(* Logix 5000 project; controller Test vendor 1 type 14 code 92 rev 33.11; software revision 33.00 *)

TASK MainTask (continuous, watchdog 500 ms) : MainProgram

MODULES
   Local : vendor 1 type 14 code 92 (ICP 0, rev 33.11)
      IN : vendor 1 type 7 code 1 (ICP 3, rev 3.2, Input RPI 20 ms)
      O : vendor 1 type 7 code 15 (ICP 2, rev 3.2, Output RPI 20 ms)
      Ethernet : 1756-ENBT (ICP 1, Ethernet 192.168.0.98, rev 6.4)
         IOLM1 : DXM (Ethernet 192.168.0.1, rev 2.22, StandardDataDriven RPI 20 ms)
END_MODULES

TYPE Banner_IOL_Port_v4 :   // UDT that has all of the data items necessary to communicate with a specific Port on a IO-Link Master
STRUCT
   Port_Controlled : INT;   // Each bit represents a port on an IO-Link Master. Set to 1 to tell AOI to control that port.
   Port_Activate : INT;   // Each bit represents a port on an IO-Link Master. When ON that port will process any commands in queue.
   Port_Read : INT;   // Each bit represents a port on an IO-Link Master. Used to determine when device AOI has requested a Read command.
   Port_Write : INT;   // Each bit represents a port on an IO-Link Master. Used to determine when device AOI has requested a Write command.
   Port_RW_Complete : INT;   // Each bit represents a port on an IO-Link Master. Tells device AOI that Read or Write request has been completed.
   Port_Device_Read : INT;
   Data_Transfer : SINT[190];   // Array to transfer data from IO-Master to device AOIs.
END_STRUCT
END_TYPE

TYPE Banner_IOLM_EL_v4 :   // Error Log for Messages to IOLM.
STRUCT
   RW : SINT;   // 0 = Read, 1 = Write.
   Port : SINT;   // Port number that generated error.
   Index : INT;   // IO-Link Index for generated error.
END_STRUCT
END_TYPE

TYPE Banner_IOLM_v4 :   // UDT to control IO-Link Masters.
STRUCT
   Message_Source_Data : SINT[190];
   Message_Destination_Data : SINT[190];
   Error_Log : Banner_IOLM_EL_v4[10];
   Error_Write_Retry : BOOL;
   Num_Error_MSGS : DINT;
   IO_Link_Master_Busy : BOOL;   // 0 = While waiting for a command, 1 = Processing command
   AOI_Reset : BOOL;
   Port_Data : Banner_IOL_Port_v4;   // All of the necessary data to work with the various ports of the IO-Link Master.
   Halt_Operation : BOOL;   // When parameter is 1 the AOI is halted as next available time frame.
   AOI_Halted : BOOL;   // AOI is in standby mode until Halt Operation tag is set back to 0.
END_STRUCT
END_TYPE

TYPE Banner_K50Pro_4State_v2 :   // Process Data for Four State Mode. This mode is only available in Touch models.
STRUCT
   Touch_Status : SINT;   // 0 = Inactive, 1 = Active. Only active for Touch models.
   In_State : SINT;   // Curent State. 0 = State 1, 1 = State 2, 2 = State 3, 3 = State 4
   Job_Control : SINT;   // 0 = Off, 1 = On
END_STRUCT
END_TYPE

TYPE Banner_K50Pro_MC_v2 :   // Process Data for Multicolor
STRUCT
   Touch_Status : SINT;   // 0 = Inactive, 1 = Active. Only active for Touch models.
   In_State : SINT;   // Curent State. 0 = State 1, 1 = State 2, 2 = State 3, 3 = State 4
   Out_State : SINT;   // Set Output State. 0 = State 1, 1 = State 2, 2 = State 3, 3 = State 4
END_STRUCT
END_TYPE

TYPE Banner_K50ProTouch_Adv_v2 :   // Advanced Process Data information for a Banner K50 Pro Touch.
STRUCT
   Touch_Status : SINT;   // 0 = Inactive, 1 = Active.
   Type : SINT;   // 0 = Off, 1 = Steady, 2 = Flash, 3 = Two Color Flash, 4 = 50/50, 5 = 50/50 Rotate, 6 = Chase, 7 = Intensity Sweep, 8 = Sequence.
   Direction : SINT;   // 0 = CCW, 1 = CW.
   Pattern : SINT;   // 0 = Flash, 1 = Strobe, 2 = Three Pulse, 3 = SOS, 4 = Random.
   Speed : SINT;   // 0 = Slow, 1 = Medium, 2 = Fast, 3 = Custom.
   Vibration_Feedback : SINT;   // 0 = Off, 1 = On, 2 = Animation Pattern. Not available in all models.
   Dynamic_Sequence : INT;   // 0 to 255. Value describing the LED position on the device.
   Sequence_Start_Location : SINT;   // 0 = LED 1, 1 = LED 2, 2 = LED 3, 3 = LED 4, 4 = LED 5, 5 = LED 6, 6 = LED 7, 7 = LED 8.
   Color_1 : SINT;   // 0 = Green, 1 = Red, 2 = Orange, 3 = Amber, 4 = Yellow, 5 = Lime Green, 6 = Spring Green, 7 = Cyan, 8 = Sky Blue, 9 = Blue, 10 = Violet, 11 = Magenta, 12 = Rose, 13 = White, 14 = Custom 1, 15 = Custom 2.
   Color_1_Intensity : SINT;   // 0 = High, 1 = Medium, 2 = Low, 3 = Off, 4 = Custom.
   Color_2 : SINT;   // 0 = Green, 1 = Red, 2 = Orange, 3 = Amber, 4 = Yellow, 5 = Lime Green, 6 = Spring Green, 7 = Cyan, 8 = Sky Blue, 9 = Blue, 10 = Violet, 11 = Magenta, 12 = Rose, 13 = White, 14 = Custom 1, 15 = Custom 2.
   Color_2_Intensity : SINT;   // 0 = High, 1 = Medium, 2 = Low, 3 = Off, 4 = Custom.
END_STRUCT
END_TYPE

TYPE Banner_K50ProTouch_LEDControl_v2 :   // LED Control Process Data for a K50 Pro Touch.
STRUCT
   Touch_Status : SINT;   // 0 = Inactive, 1 = Active.
   LED_1_Color : SINT;   // 0 = Green, 1 = Red, 2 = Orange, 3 = Amber, 4 = Yellow, 5 = Lime Green, 6 = Spring Green, 7 = Cyan, 8 = Sky Blue, 9 = Blue, 10 = Violet, 11 = Magenta, 12 = Rose, 13 = White, 14 = Custom 1, 15 = Custom 2.
   LED_1_Intensity : SINT;   // 0 to 10 (0 to 100%).
   LED_2_Color : SINT;   // 0 = Green, 1 = Red, 2 = Orange, 3 = Amber, 4 = Yellow, 5 = Lime Green, 6 = Spring Green, 7 = Cyan, 8 = Sky Blue, 9 = Blue, 10 = Violet, 11 = Magenta, 12 = Rose, 13 = White, 14 = Custom 1, 15 = Custom 2.
   LED_2_Intensity : SINT;   // 0 to 10 (0 to 100%).
   LED_3_Color : SINT;   // 0 = Green, 1 = Red, 2 = Orange, 3 = Amber, 4 = Yellow, 5 = Lime Green, 6 = Spring Green, 7 = Cyan, 8 = Sky Blue, 9 = Blue, 10 = Violet, 11 = Magenta, 12 = Rose, 13 = White, 14 = Custom 1, 15 = Custom 2.
   LED_3_Intensity : SINT;   // 0 to 10 (0 to 100%).
   LED_4_Color : SINT;   // 0 = Green, 1 = Red, 2 = Orange, 3 = Amber, 4 = Yellow, 5 = Lime Green, 6 = Spring Green, 7 = Cyan, 8 = Sky Blue, 9 = Blue, 10 = Violet, 11 = Magenta, 12 = Rose, 13 = White, 14 = Custom 1, 15 = Custom 2.
   LED_4_Intensity : SINT;   // 0 to 10 (0 to 100%).
   LED_5_Color : SINT;   // 0 = Green, 1 = Red, 2 = Orange, 3 = Amber, 4 = Yellow, 5 = Lime Green, 6 = Spring Green, 7 = Cyan, 8 = Sky Blue, 9 = Blue, 10 = Violet, 11 = Magenta, 12 = Rose, 13 = White, 14 = Custom 1, 15 = Custom 2.
   LED_5_Intensity : SINT;   // 0 to 10 (0 to 100%).
   LED_6_Color : SINT;   // 0 = Green, 1 = Red, 2 = Orange, 3 = Amber, 4 = Yellow, 5 = Lime Green, 6 = Spring Green, 7 = Cyan, 8 = Sky Blue, 9 = Blue, 10 = Violet, 11 = Magenta, 12 = Rose, 13 = White, 14 = Custom 1, 15 = Custom 2.
   LED_6_Intensity : SINT;   // 0 to 10 (0 to 100%).
   LED_7_Color : SINT;   // 0 = Green, 1 = Red, 2 = Orange, 3 = Amber, 4 = Yellow, 5 = Lime Green, 6 = Spring Green, 7 = Cyan, 8 = Sky Blue, 9 = Blue, 10 = Violet, 11 = Magenta, 12 = Rose, 13 = White, 14 = Custom 1, 15 = Custom 2.
   LED_7_Intensity : SINT;   // 0 to 10 (0 to 100%).
   LED_8_Color : SINT;   // 0 = Green, 1 = Red, 2 = Orange, 3 = Amber, 4 = Yellow, 5 = Lime Green, 6 = Spring Green, 7 = Cyan, 8 = Sky Blue, 9 = Blue, 10 = Violet, 11 = Magenta, 12 = Rose, 13 = White, 14 = Custom 1, 15 = Custom 2.
   LED_8_Intensity : SINT;   // 0 to 10 (0 to 100%).
   Vibration_Feedback : SINT;   // 0 = Off, 1 = On, 2 = Pattern.
   Vibration_Pattern : SINT;   // 0 = Off, 1 = On, 2 = 3 Pulses, 3 = SOS, 4 = Random.
   Vibration_Speed : SINT;   // 0 = Slow, 1 = Medium, 2 = Fast, 3 = Custom.
END_STRUCT
END_TYPE

TYPE Banner_K50ProTouch_PDIO_v2 :   // UDT that records the converted prcoess data.
STRUCT
   PD_MultiColor_State : Banner_K50Pro_MC_v2;   // Only active when Operation Mode set to 0. State tells the light which of the four states it should be in. 0 = State 1, 1 = State 2, 2 = State 3, 3 = State 4.
   PD_FourState_Job_Input : Banner_K50Pro_4State_v2;   // Only active when Operation Mode set to 1. Job Input tells the light how it should behave. 0 - Off, 1 = ON
   PD_Advanced : Banner_K50ProTouch_Adv_v2;   // Only active when Operation Mode set to 2.
   PD_LED : Banner_K50ProTouch_LEDControl_v2;   // Only active when Operation Mode set to 3.
   PDO_DT : SINT[10];
   PDI_DT : SINT[2];
END_STRUCT
END_TYPE

TYPE Banner_K50ProTouch_RD_v2 :   // UDT with all of the Read only parameters for K50 Pro Touch.
STRUCT
   Master_Cycle_Time : INT;
   Min_Cycle_Time : INT;
   M_Sequence_Capability : INT;
   IO_Link_Version_ID : INT;
   Process_Data_Input_Length : INT;
   Process_Data_Output_Length : INT;
   Combined_Vendor_ID : DINT;   // IO-Link Vendor ID
   Vendor_ID1 : INT;
   Vendor_ID2 : INT;
   Combined_Device_ID : DINT;   // IO-Link Device ID
   Device_ID1 : INT;
   Device_ID2 : INT;
   Device_ID3 : INT;
   Serial_Number : STRING;
END_STRUCT
END_TYPE

TYPE Banner_K50ProTouch_SP_v2 :   // UDT for K50 Pro Touch with the State Parameters structure.
STRUCT
   Type : SINT;   // 0 = Off, 1 = Steady, 2 = Flash, 3 = Two Color Flash, 4 = 50/50, 5 = 50/50 Rotate, 6 = Chase, 7 = Intensity Sweep, 8 = Sequence.
   Direction : SINT;   // 0 = CCW, 1 = CW.
   Pattern : SINT;   // 0 = Flash, 1 = Strobe, 2 = Three Pulse, 3 = SOS, 4 = Random.
   Speed : SINT;   // 0 = Slow, 1 = Medium, 2 = Fast, 3 = Custom.
   Vibration_Feedback : SINT;   // 0 = Off, 1 = On, 2 = Pattern. Not available in all models.
   Off_Delay_Type : SINT;   // 0 =Leading Edge, 1 = Trailing Edge.
   Off_Delay : DINT;   // 0 to 65535 in ms. Length of time before the device returns to 'touch inactive' state after button is released.
   Static_Sequence : INT;   // 0 to 255. Value describing the LED position of the device.
   Sequence_Start_Location : SINT;   // 0 = LED1, 1 = LED2, 2 = LED3, 3 = LED4, 4 = LED5, 5 = LED6, 6 = LED7, 7 = LED8.
   Color_1 : SINT;   // 0 = Green, 1 = Red, 2 = Orange, 3 = Amber, 4 = Yellow, 5 = Lime Green, 6 = Spring Green, 7 = Cyan, 8 = SKy Blue, 9 = Blue, 10 = Violet, 11 = Magenta, 12 = Rose, 13 = White, 14 Custom 1, 15 = Custom 2.
   Color_1_Intensity : SINT;   // 0 = High, 1 = Medium, 2 = Low, 3 = Off, 4 = Custom.
   Color_2 : SINT;   // 0 = Green, 1 = Red, 2 = Orange, 3 = Amber, 4 = Yellow, 5 = Lime Green, 6 = Spring Green, 7 = Cyan, 8 = SKy Blue, 9 = Blue, 10 = Violet, 11 = Magenta, 12 = Rose, 13 = White, 14 Custom 1, 15 = Custom 2.
   Color_2_Intensity : SINT;   // 0 = High, 1 = Medium, 2 = Low, 3 = Off, 4 = Custom.
END_STRUCT
END_TYPE

TYPE Banner_K50ProTouch_v2 :   // UDT with all of the parameters for K50 Pro Touch.
STRUCT
   Initial_Global_Read : BOOL;   // Determines if all of the IO-Link data has been read into the PLC yet
   Command : INT;   // Value placed in here will activate a read or write to a specifc IO-Link Index
   Read_Data : Banner_K50ProTouch_RD_v2;   // All read data
   Write_Data : Banner_K50ProTouch_WD_v2;   // All data that can be written to.
   Archive : Banner_K50ProTouch_WD_v2;   // Archive of the write data.
   Reset : BOOL;
END_STRUCT
END_TYPE

TYPE Banner_K50ProTouch_WD_v2 :   // UDT that stores the Write Data for a K50 Pro Touch.
STRUCT
   System_Command : INT;   // See IODD file for list of commands that can be activated via the System Command interface
   Parameter_Access_Lock : SINT;   // Write access to all read/write parameters is block when this bit is ON.
   Data_Storage_Lock : SINT;   // Data storage mechanism is inhibited when bit is ON.
   Local_Parameterization_Lock : SINT;   // Parameteriation via local control elementes is inhibited.
   Local_User_Interface_Lock : SINT;   // Operation of the hmi on the device is disabled.
   Operation_Mode : SINT;   // 0 = Multicolor, 1 = Four State Full Logic, 2 = Advanced, 3 = LED Control, 4 = Demo.
   Custom_Intensity : SINT;   // 0 to 100 %
   Custom_Flash_Rate : INT;   // Range 5 to 200 (.5 to 20 converted rate).
   Restrict_to_Gamut : SINT;   // 0 = Off, 1 = On.
   Touch_Sensitivity : SINT;   // 0 = Low, 1 = High.
   Function : SINT;   // 0 = Momentary, 1 = Latched.
   Mute_Enable : SINT;   // 0 = Off, 1 = On.
   On_Delay : DINT;   // 0 to 65535 in ms. Length of time the touch button needs to be pressed to trigger touch active state.
   Output_State : SINT;   // 0 = NO, 1 = NC.
   Off_Delay_Type : SINT;   // 0 = Leading Edge, 1 = Trailing Edge.
   Off_Delay : DINT;   // 0 to 65535 in ms. Length of time before the device returns to the 'touch inactive' state after button is released.
   State_Parameters : Banner_K50ProTouch_SP_v2[5];   // State Parameters. 1 through 4 will have values.
   CC1_Red : INT;   // 0-255. Custom 1 Red.
   CC1_Green : INT;   // 0-255. Custom 1 Green.
   CC1_Blue : INT;   // 0-255. Custom 1 Blue.
   CC2_Red : INT;   // 0-255. Custom 2 Red.
   CC2_Green : INT;   // 0-255. Custom 2 Green.
   CC_Blue : INT;   // 0-255. Custom 2 Blue.
END_STRUCT
END_TYPE

ADD_ON_INSTRUCTION Banner_DXMR90_IOLM_v4   (* revision 4.1, vendor Banner Engineering *)
// AOI that controls a Banner IO-Link Master with Banner devices.
// Revision note:
// Revised operational order for ISDU write.
VAR_IN_OUT
   IOLM : Banner_IOLM_v4; {required}
END_VAR
VAR
   Lock : DINT; {access None}
   Byte_Length : SINT; {access None}
   Current_Port : INT; {access None}   // Current port to communicate with via the IO-Link Master.
   Timer : TIMER := (PRE := 500); {access None}
   Error_Index : DINT; {access None}
   Timer2 : TIMER := (PRE := 5000); {access None}
   Temp_Index : INT; {access None}
   ErrCount : DINT; {access None}
   Timer4 : TIMER := (PRE := 2000); {access None}
   Timer5 : TIMER := (PRE := 2000); {access None}
   Timer3 : TIMER := (PRE := 2000); {access None}
   Timer6 : TIMER := (PRE := 3000); {access None}
   Timer7 : TIMER := (PRE := 3000); {access None}
END_VAR

ROUTINE Logic   (* ladder *)
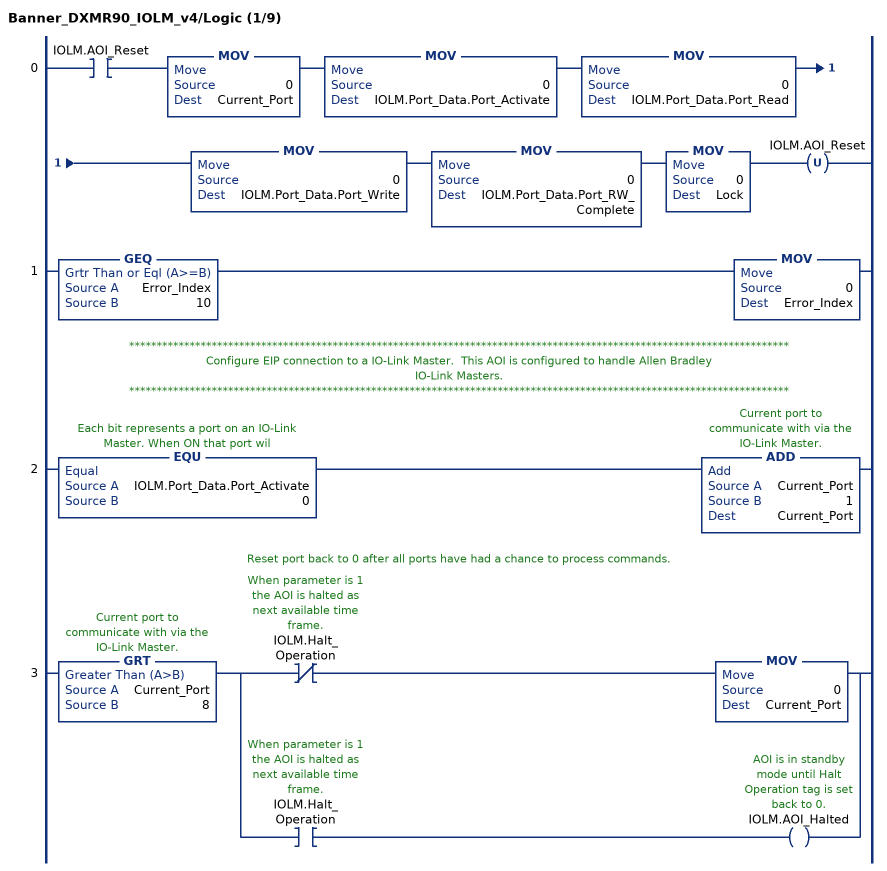
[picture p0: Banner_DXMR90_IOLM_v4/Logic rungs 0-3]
   0: XIC(IOLM.AOI_Reset)MOV(0,Current_Port)MOV(0,IOLM.Port_Data.Port_Activate)MOV(0,IOLM.Port_Data.Port_Read)MOV(0,IOLM.Port_Data.Port_Write)MOV(0,IOLM.Port_Data.Port_RW_Complete)MOV(0,Lock)OTU(IOLM.AOI_Reset);
   1: GEQ(Error_Index,10)MOV(0,Error_Index);
   // ************************************************************************************************************************
   // Configure EIP connection to a IO-Link Master.  This AOI is configured to handle Allen Bradley
   // IO-Link Masters.
   // ************************************************************************************************************************
   2: EQU(IOLM.Port_Data.Port_Activate,0)ADD(Current_Port,1,Current_Port);
   // Reset port back to 0 after all ports have had a chance to process commands.
   3: GRT(Current_Port,8)[XIO(IOLM.Halt_Operation) MOV(0,Current_Port) ,XIC(IOLM.Halt_Operation) OTE(IOLM.AOI_Halted) ];
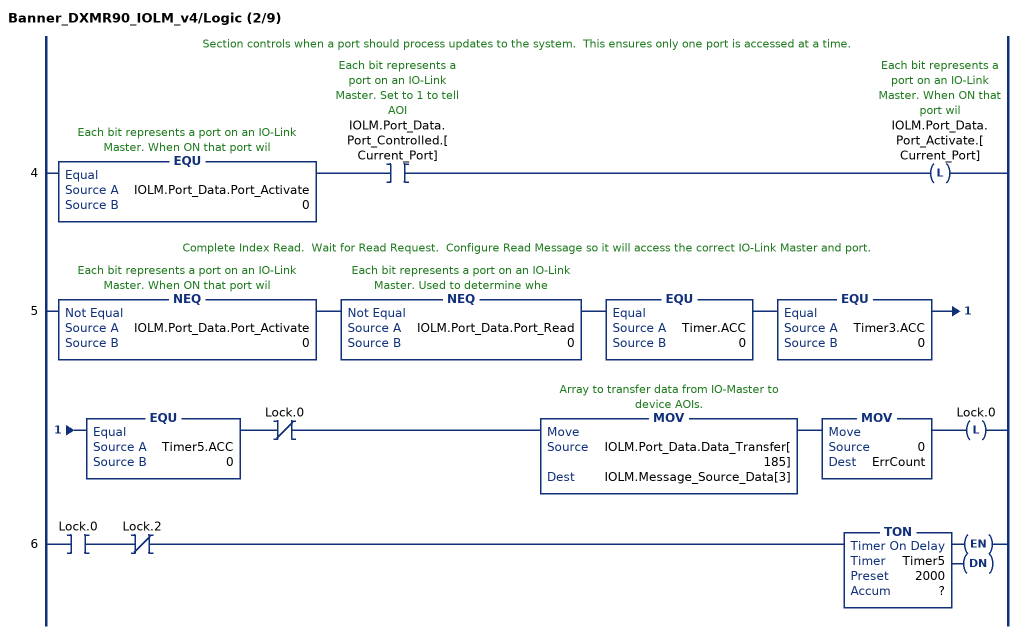
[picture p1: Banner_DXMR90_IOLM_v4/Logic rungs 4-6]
   // Section controls when a port should process updates to the system.  This ensures only one port is accessed at a time.
   4: EQU(IOLM.Port_Data.Port_Activate,0)XIC(IOLM.Port_Data.Port_Controlled.[Current_Port])OTL(IOLM.Port_Data.Port_Activate.[Current_Port]);
   // Complete Index Read.  Wait for Read Request.  Configure Read Message so it will access the correct IO-Link Master and port.
   5: NEQ(IOLM.Port_Data.Port_Activate,0)NEQ(IOLM.Port_Data.Port_Read,0)EQU(Timer.ACC,0)EQU(Timer3.ACC,0)EQU(Timer5.ACC,0)XIO(Lock.0)MOV(IOLM.Port_Data.Data_Transfer[185],IOLM.Message_Source_Data[3])MOV(0,ErrCount)OTL(Lock.0);
   6: XIC(Lock.0)XIO(Lock.2)TON(Timer5,?,?);
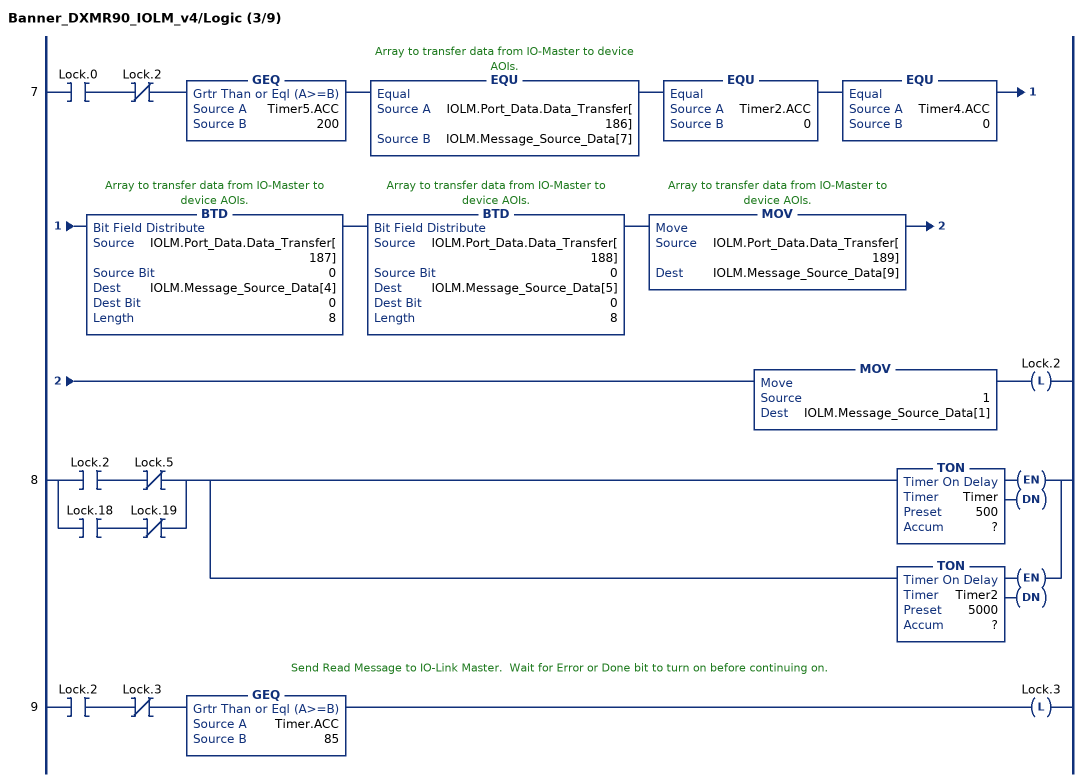
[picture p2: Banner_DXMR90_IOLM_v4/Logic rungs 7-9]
   7: XIC(Lock.0)XIO(Lock.2)GEQ(Timer5.ACC,200)EQU(IOLM.Port_Data.Data_Transfer[186],IOLM.Message_Source_Data[7])EQU(Timer2.ACC,0)EQU(Timer4.ACC,0)BTD(IOLM.Port_Data.Data_Transfer[187],0,IOLM.Message_Source_Data[4],0,8)BTD(IOLM.Port_Data.Data_Transfer[188],0,IOLM.Message_Source_Data[5],0,8)MOV(IOLM.Port_Data.Data_Transfer[189],IOLM.Message_Source_Data[9])MOV(1,IOLM.Message_Source_Data[1])OTL(Lock.2);
   8: [XIC(Lock.2) XIO(Lock.5) ,XIC(Lock.18) XIO(Lock.19) ][TON(Timer,?,?) ,TON(Timer2,?,?) ];
   // Send Read Message to IO-Link Master.  Wait for Error or Done bit to turn on before continuing on.
   9: XIC(Lock.2)XIO(Lock.3)GEQ(Timer.ACC,85)OTL(Lock.3);
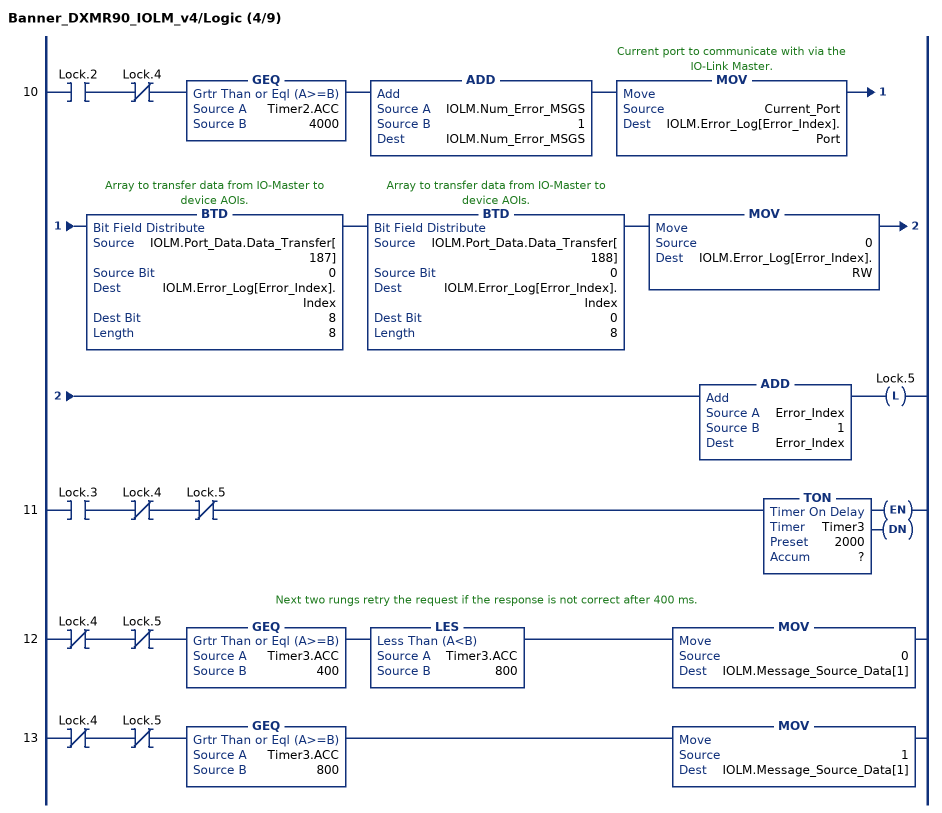
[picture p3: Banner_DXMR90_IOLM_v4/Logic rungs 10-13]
   10: XIC(Lock.2)XIO(Lock.4)GEQ(Timer2.ACC,4000)ADD(IOLM.Num_Error_MSGS,1,IOLM.Num_Error_MSGS)MOV(Current_Port,IOLM.Error_Log[Error_Index].Port)BTD(IOLM.Port_Data.Data_Transfer[187],0,IOLM.Error_Log[Error_Index].Index,8,8)BTD(IOLM.Port_Data.Data_Transfer[188],0,IOLM.Error_Log[Error_Index].Index,0,8)MOV(0,IOLM.Error_Log[Error_Index].RW)ADD(Error_Index,1,Error_Index)OTL(Lock.5);
   11: XIC(Lock.3)XIO(Lock.4)XIO(Lock.5)TON(Timer3,?,?);
   // Next two rungs retry the request if the response is not correct after 400 ms.
   12: XIO(Lock.4)XIO(Lock.5)GEQ(Timer3.ACC,400)LES(Timer3.ACC,800)MOV(0,IOLM.Message_Source_Data[1]);
   13: XIO(Lock.4)XIO(Lock.5)GEQ(Timer3.ACC,800)MOV(1,IOLM.Message_Source_Data[1]);
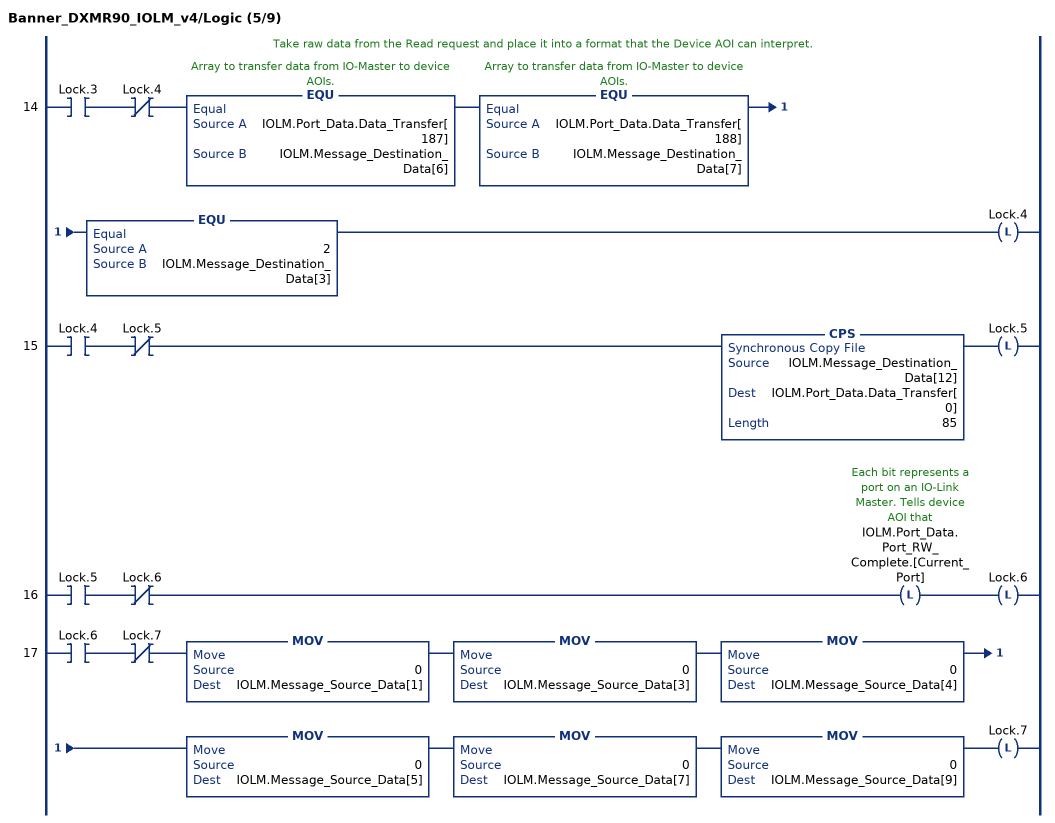
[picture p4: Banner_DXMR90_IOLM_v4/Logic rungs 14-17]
   // Take raw data from the Read request and place it into a format that the Device AOI can interpret.
   14: XIC(Lock.3)XIO(Lock.4)EQU(IOLM.Port_Data.Data_Transfer[187],IOLM.Message_Destination_Data[6])EQU(IOLM.Port_Data.Data_Transfer[188],IOLM.Message_Destination_Data[7])EQU(2,IOLM.Message_Destination_Data[3])OTL(Lock.4);
   15: XIC(Lock.4)XIO(Lock.5)CPS(IOLM.Message_Destination_Data[12],IOLM.Port_Data.Data_Transfer[0],85)OTL(Lock.5);
   16: XIC(Lock.5)XIO(Lock.6)OTL(IOLM.Port_Data.Port_RW_Complete.[Current_Port])OTL(Lock.6);
   17: XIC(Lock.6)XIO(Lock.7)MOV(0,IOLM.Message_Source_Data[1])MOV(0,IOLM.Message_Source_Data[3])MOV(0,IOLM.Message_Source_Data[4])MOV(0,IOLM.Message_Source_Data[5])MOV(0,IOLM.Message_Source_Data[7])MOV(0,IOLM.Message_Source_Data[9])OTL(Lock.7);
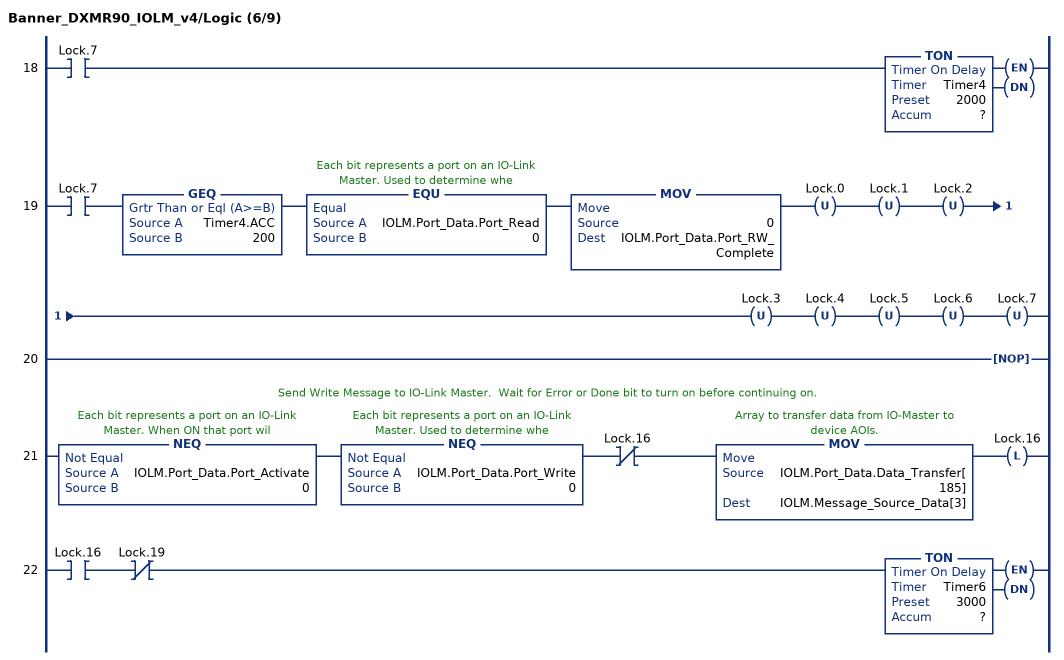
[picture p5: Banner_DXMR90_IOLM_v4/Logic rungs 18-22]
   18: XIC(Lock.7)TON(Timer4,?,?);
   19: XIC(Lock.7)GEQ(Timer4.ACC,200)EQU(IOLM.Port_Data.Port_Read,0)MOV(0,IOLM.Port_Data.Port_RW_Complete)OTU(Lock.0)OTU(Lock.1)OTU(Lock.2)OTU(Lock.3)OTU(Lock.4)OTU(Lock.5)OTU(Lock.6)OTU(Lock.7);
   20: NOP();
   // Send Write Message to IO-Link Master.  Wait for Error or Done bit to turn on before continuing on.
   21: NEQ(IOLM.Port_Data.Port_Activate,0)NEQ(IOLM.Port_Data.Port_Write,0)XIO(Lock.16)MOV(IOLM.Port_Data.Data_Transfer[185],IOLM.Message_Source_Data[3])OTL(Lock.16);
   22: XIC(Lock.16)XIO(Lock.19)TON(Timer6,?,?);
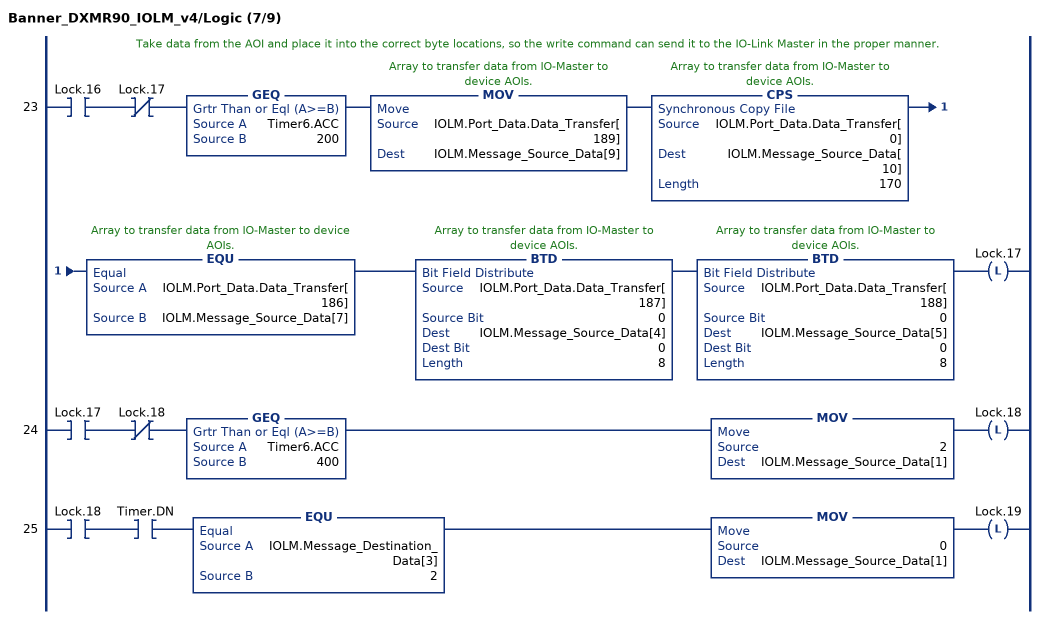
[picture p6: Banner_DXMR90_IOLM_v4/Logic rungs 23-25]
   // Take data from the AOI and place it into the correct byte locations, so the write command can send it to the IO-Link Master in the proper manner.
   23: XIC(Lock.16)XIO(Lock.17)GEQ(Timer6.ACC,200)MOV(IOLM.Port_Data.Data_Transfer[189],IOLM.Message_Source_Data[9])CPS(IOLM.Port_Data.Data_Transfer[0],IOLM.Message_Source_Data[10],170)EQU(IOLM.Port_Data.Data_Transfer[186],IOLM.Message_Source_Data[7])BTD(IOLM.Port_Data.Data_Transfer[187],0,IOLM.Message_Source_Data[4],0,8)BTD(IOLM.Port_Data.Data_Transfer[188],0,IOLM.Message_Source_Data[5],0,8)OTL(Lock.17);
   24: XIC(Lock.17)XIO(Lock.18)GEQ(Timer6.ACC,400)MOV(2,IOLM.Message_Source_Data[1])OTL(Lock.18);
   25: XIC(Lock.18)XIC(Timer.DN)EQU(IOLM.Message_Destination_Data[3],2)MOV(0,IOLM.Message_Source_Data[1])OTL(Lock.19);
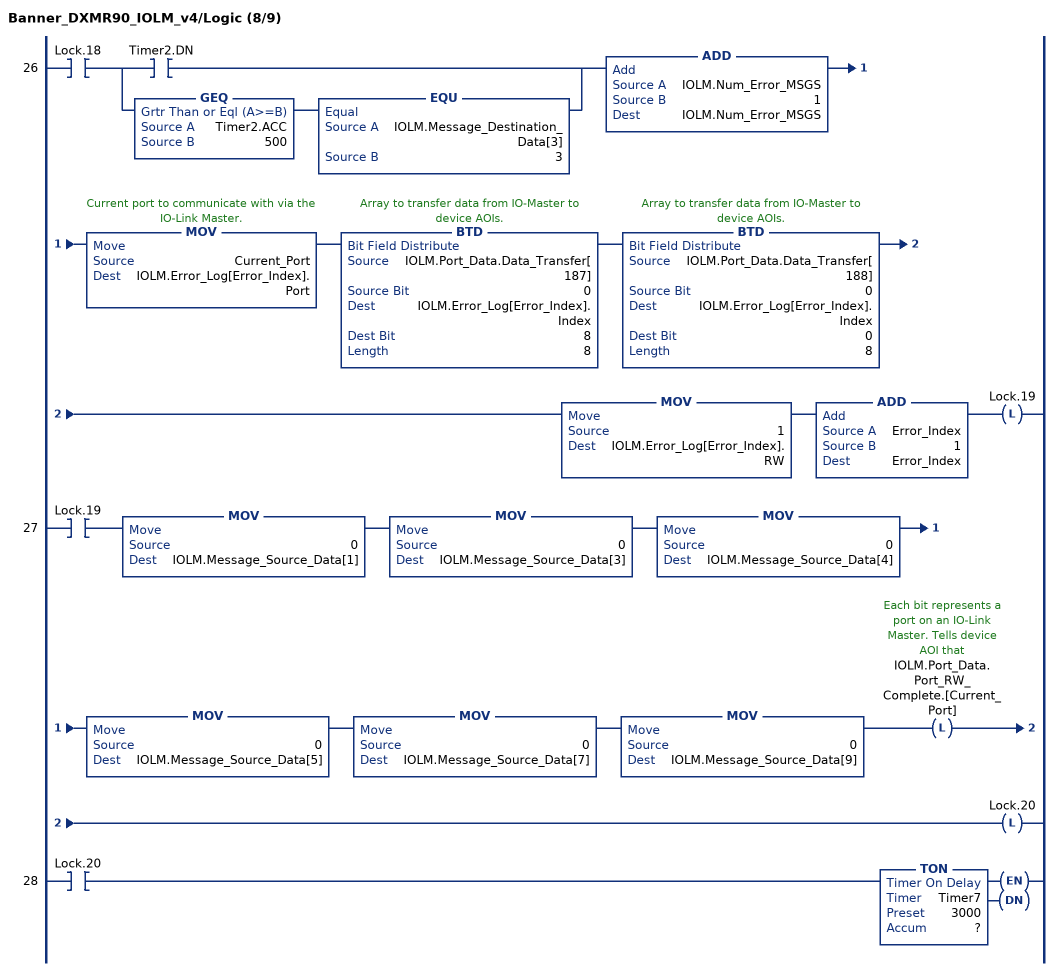
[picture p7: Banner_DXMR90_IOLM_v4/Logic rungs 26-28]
   26: XIC(Lock.18)[XIC(Timer2.DN) ,GEQ(Timer2.ACC,500) EQU(IOLM.Message_Destination_Data[3],3) ]ADD(IOLM.Num_Error_MSGS,1,IOLM.Num_Error_MSGS)MOV(Current_Port,IOLM.Error_Log[Error_Index].Port)BTD(IOLM.Port_Data.Data_Transfer[187],0,IOLM.Error_Log[Error_Index].Index,8,8)BTD(IOLM.Port_Data.Data_Transfer[188],0,IOLM.Error_Log[Error_Index].Index,0,8)MOV(1,IOLM.Error_Log[Error_Index].RW)ADD(Error_Index,1,Error_Index)OTL(Lock.19);
   27: XIC(Lock.19)MOV(0,IOLM.Message_Source_Data[1])MOV(0,IOLM.Message_Source_Data[3])MOV(0,IOLM.Message_Source_Data[4])MOV(0,IOLM.Message_Source_Data[5])MOV(0,IOLM.Message_Source_Data[7])MOV(0,IOLM.Message_Source_Data[9])OTL(IOLM.Port_Data.Port_RW_Complete.[Current_Port])OTL(Lock.20);
   28: XIC(Lock.20)TON(Timer7,?,?);
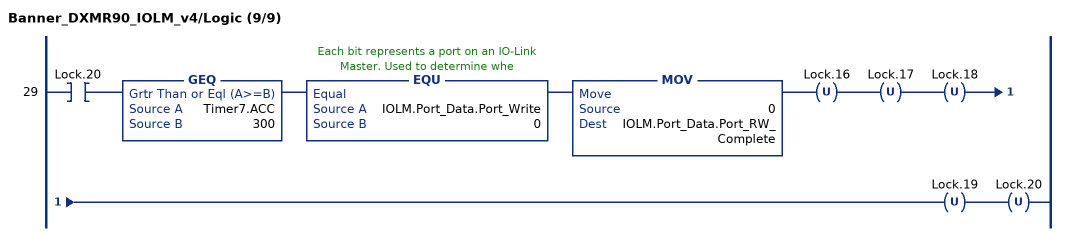
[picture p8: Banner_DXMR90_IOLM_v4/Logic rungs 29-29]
   29: XIC(Lock.20)GEQ(Timer7.ACC,300)EQU(IOLM.Port_Data.Port_Write,0)MOV(0,IOLM.Port_Data.Port_RW_Complete)OTU(Lock.16)OTU(Lock.17)OTU(Lock.18)OTU(Lock.19)OTU(Lock.20);
END_ROUTINE
END_ADD_ON_INSTRUCTION

ADD_ON_INSTRUCTION Banner_K50ProTouch_Param_v4   (* revision 4.0, vendor Banner Engineering *)
// AOI to read and write parameter data to an IO-Link K50 Pro Touch.
VAR_IN_OUT
   K50ProTouch : Banner_K50ProTouch_v2; {required}
   Port_Data : Banner_IOL_Port_v4; {required}
END_VAR
VAR_INPUT
   Port : DINT; {required}
END_VAR
VAR
   Local_Control : DINT; {access None}
   Global_Read_Command_Value : INT; {access None}
   Global_Write_Command_Value : INT; {access None}
   Command_Being_Processed : BOOL; {access None}
   Update_Archive : BOOL; {access None}
   Index_Write_Control : DINT; {access None}
   Index_Write_Inprocess : INT; {access None}
   Temp_Excess_Gain : DINT[2]; {access None}
   Inprocess_Index : DINT; {access None}
   SP_Index : DINT; {access None}   // State Parameters Index
   SP_Write_Index : DINT; {access None}
   SP_R_Index : DINT; {access None}
   SP_W_Index : DINT; {access None}
END_VAR

ROUTINE Logic   (* ladder *)
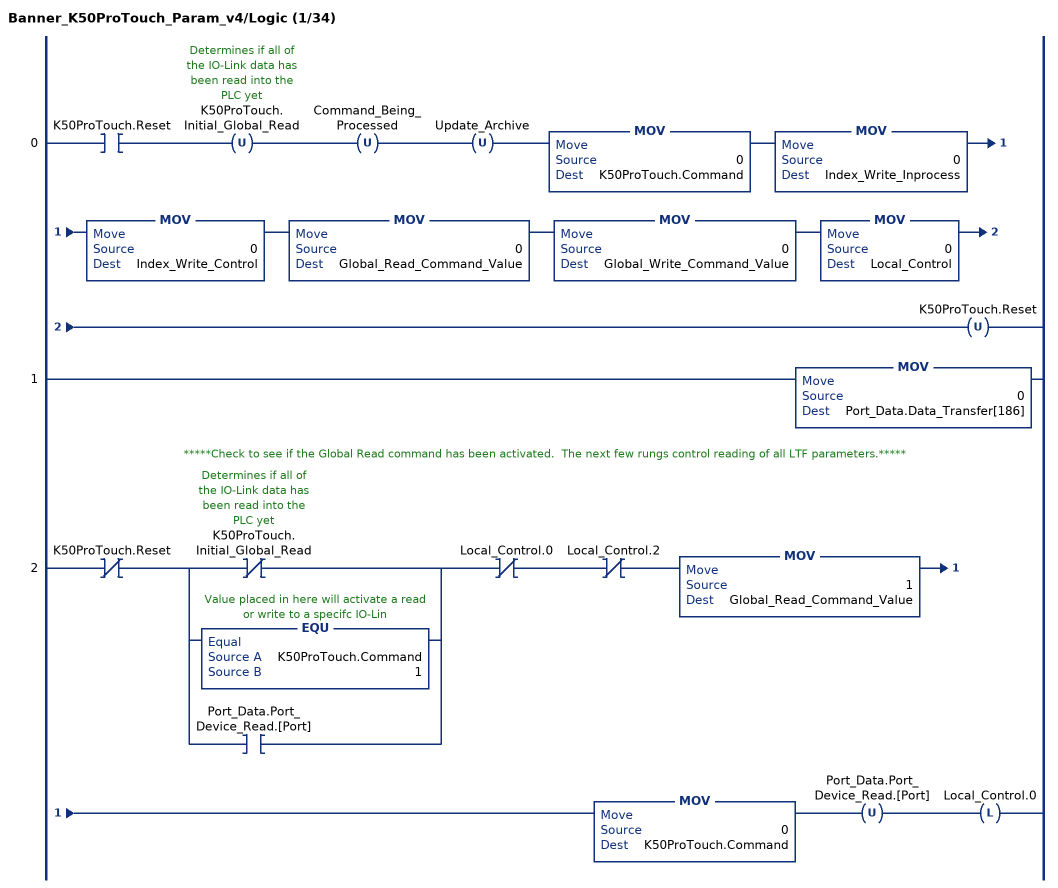
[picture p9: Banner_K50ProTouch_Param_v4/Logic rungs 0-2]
   0: XIC(K50ProTouch.Reset)OTU(K50ProTouch.Initial_Global_Read)OTU(Command_Being_Processed)OTU(Update_Archive)MOV(0,K50ProTouch.Command)MOV(0,Index_Write_Inprocess)MOV(0,Index_Write_Control)MOV(0,Global_Read_Command_Value)MOV(0,Global_Write_Command_Value)MOV(0,Local_Control)OTU(K50ProTouch.Reset);
   1: MOV(0,Port_Data.Data_Transfer[186]);
   // *****Check to see if the Global Read command has been activated.  The next few rungs control reading of all LTF parameters.*****
   2: XIO(K50ProTouch.Reset)[XIO(K50ProTouch.Initial_Global_Read) ,EQU(K50ProTouch.Command,1) ,XIC(Port_Data.Port_Device_Read.[Port]) ]XIO(Local_Control.0)XIO(Local_Control.2)MOV(1,Global_Read_Command_Value)MOV(0,K50ProTouch.Command)OTU(Port_Data.Port_Device_Read.[Port])OTL(Local_Control.0);
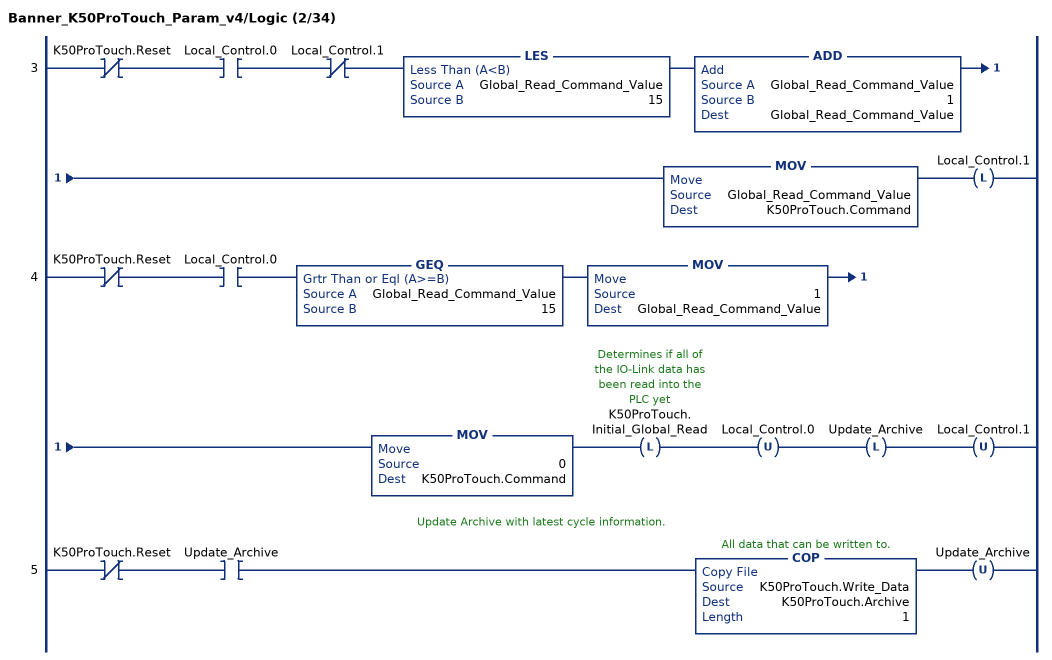
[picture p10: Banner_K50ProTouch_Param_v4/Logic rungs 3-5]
   3: XIO(K50ProTouch.Reset)XIC(Local_Control.0)XIO(Local_Control.1)LES(Global_Read_Command_Value,15)ADD(Global_Read_Command_Value,1,Global_Read_Command_Value)MOV(Global_Read_Command_Value,K50ProTouch.Command)OTL(Local_Control.1);
   4: XIO(K50ProTouch.Reset)XIC(Local_Control.0)GEQ(Global_Read_Command_Value,15)MOV(1,Global_Read_Command_Value)MOV(0,K50ProTouch.Command)OTL(K50ProTouch.Initial_Global_Read)OTU(Local_Control.0)OTL(Update_Archive)OTU(Local_Control.1);
   // Update Archive with latest cycle information.
   5: XIO(K50ProTouch.Reset)XIC(Update_Archive)COP(K50ProTouch.Write_Data,K50ProTouch.Archive,1)OTU(Update_Archive);
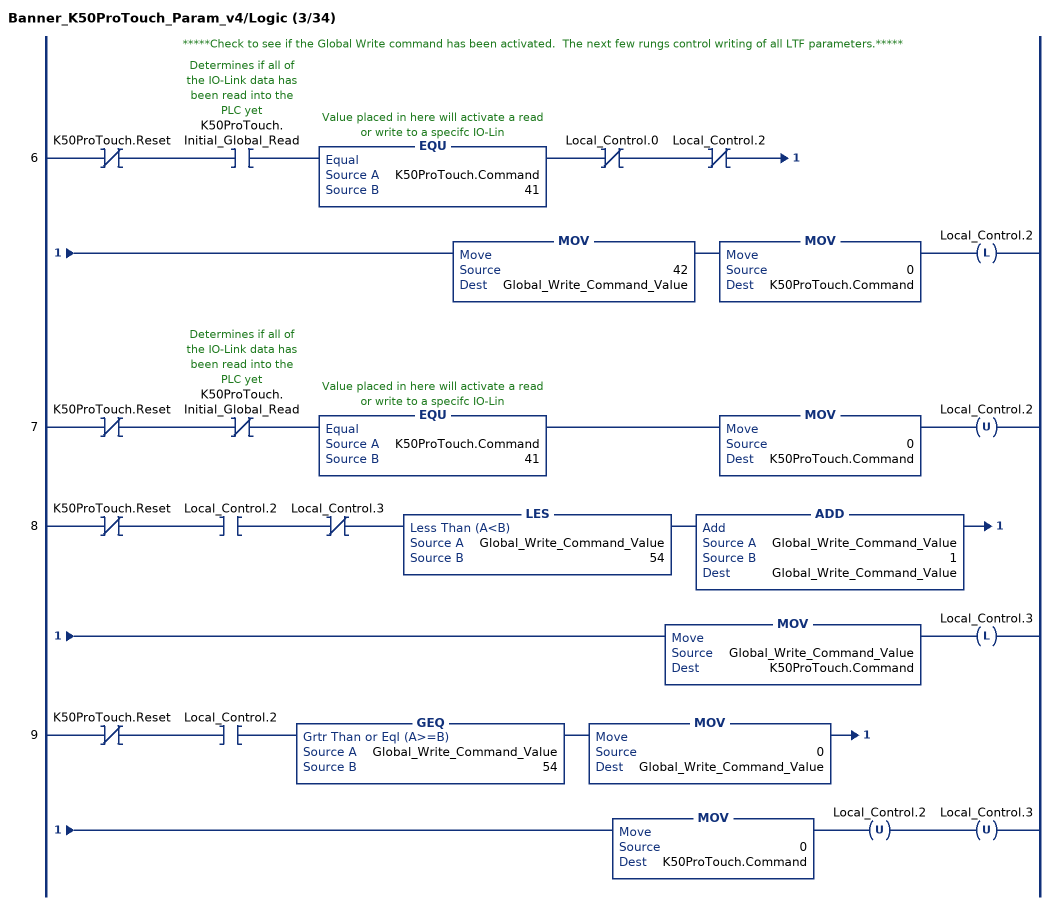
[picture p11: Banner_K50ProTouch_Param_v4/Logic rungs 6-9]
   // *****Check to see if the Global Write command has been activated.  The next few rungs control writing of all LTF parameters.*****
   6: XIO(K50ProTouch.Reset)XIC(K50ProTouch.Initial_Global_Read)EQU(K50ProTouch.Command,41)XIO(Local_Control.0)XIO(Local_Control.2)MOV(42,Global_Write_Command_Value)MOV(0,K50ProTouch.Command)OTL(Local_Control.2);
   7: XIO(K50ProTouch.Reset)XIO(K50ProTouch.Initial_Global_Read)EQU(K50ProTouch.Command,41)MOV(0,K50ProTouch.Command)OTU(Local_Control.2);
   8: XIO(K50ProTouch.Reset)XIC(Local_Control.2)XIO(Local_Control.3)LES(Global_Write_Command_Value,54)ADD(Global_Write_Command_Value,1,Global_Write_Command_Value)MOV(Global_Write_Command_Value,K50ProTouch.Command)OTL(Local_Control.3);
   9: XIO(K50ProTouch.Reset)XIC(Local_Control.2)GEQ(Global_Write_Command_Value,54)MOV(0,Global_Write_Command_Value)MOV(0,K50ProTouch.Command)OTU(Local_Control.2)OTU(Local_Control.3);
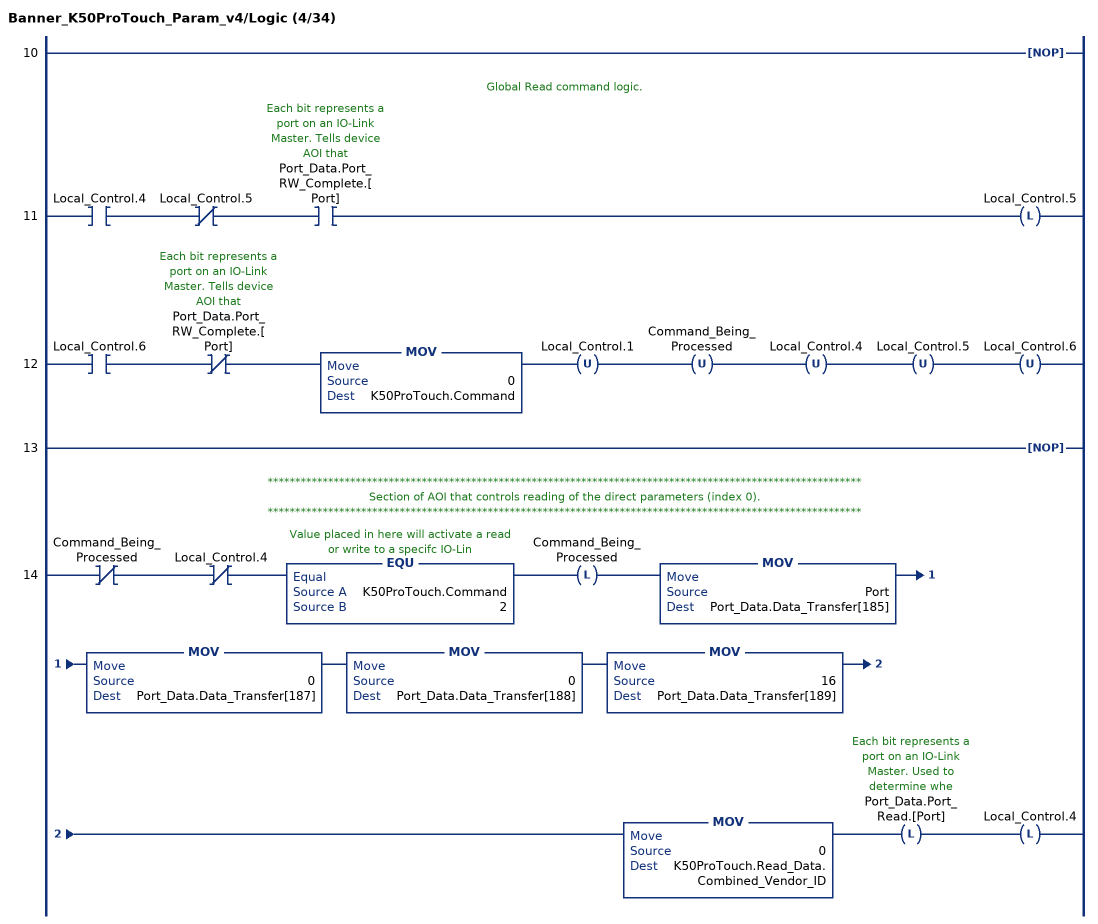
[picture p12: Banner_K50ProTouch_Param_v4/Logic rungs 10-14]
   10: NOP();
   // Global Read command logic.
   11: XIC(Local_Control.4)XIO(Local_Control.5)XIC(Port_Data.Port_RW_Complete.[Port])OTL(Local_Control.5);
   12: XIC(Local_Control.6)XIO(Port_Data.Port_RW_Complete.[Port])MOV(0,K50ProTouch.Command)OTU(Local_Control.1)OTU(Command_Being_Processed)OTU(Local_Control.4)OTU(Local_Control.5)OTU(Local_Control.6);
   13: NOP();
   // ************************************************************************************************************
   // Section of AOI that controls reading of the direct parameters (index 0).
   // ************************************************************************************************************
   14: XIO(Command_Being_Processed)XIO(Local_Control.4)EQU(K50ProTouch.Command,2)OTL(Command_Being_Processed)MOV(Port,Port_Data.Data_Transfer[185])MOV(0,Port_Data.Data_Transfer[187])MOV(0,Port_Data.Data_Transfer[188])MOV(16,Port_Data.Data_Transfer[189])MOV(0,K50ProTouch.Read_Data.Combined_Vendor_ID)OTL(Port_Data.Port_Read.[Port])OTL(Local_Control.4);
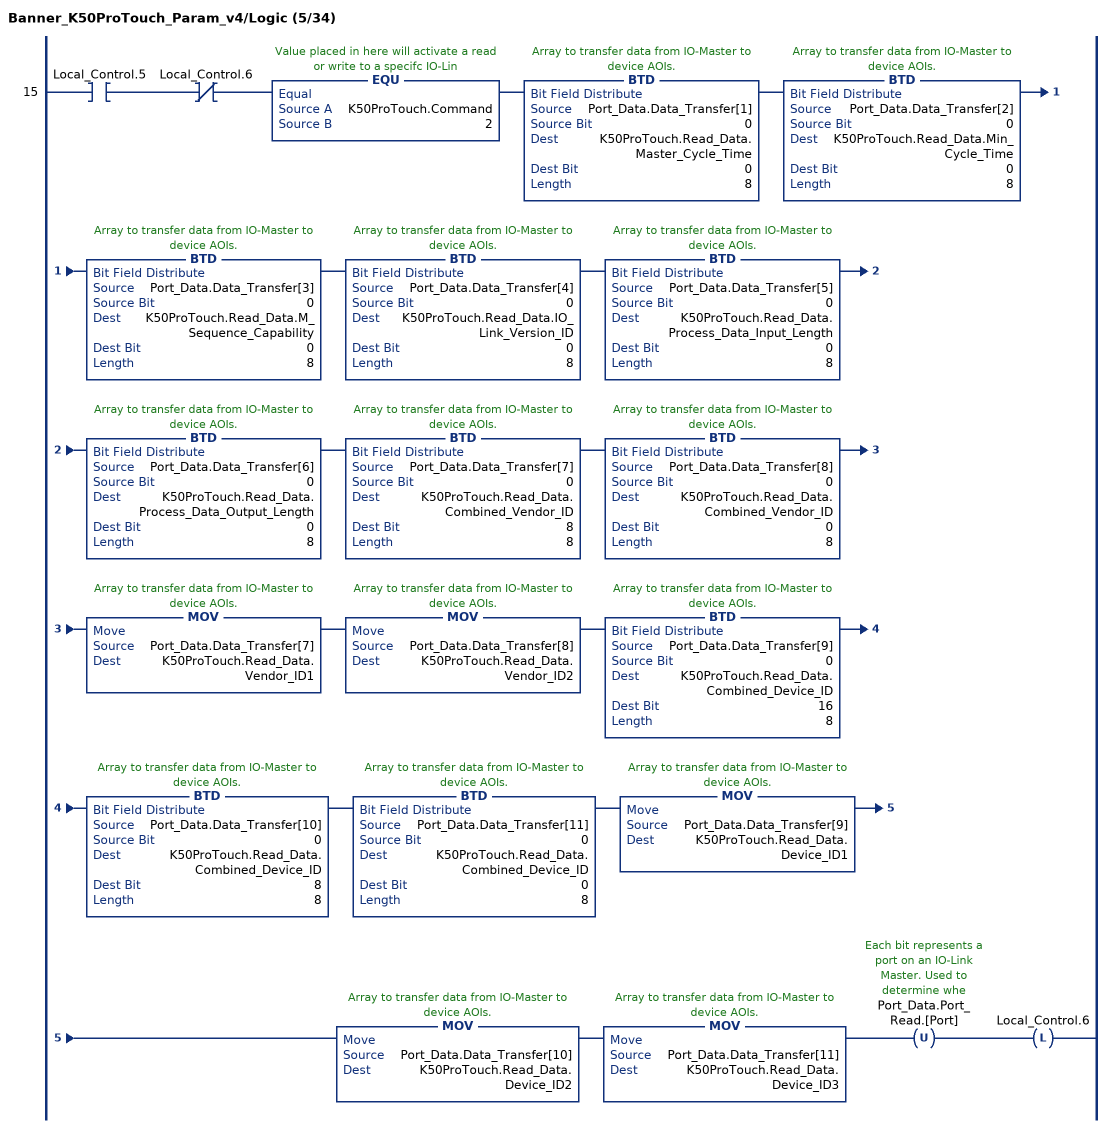
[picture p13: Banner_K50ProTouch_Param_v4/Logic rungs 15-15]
   15: XIC(Local_Control.5)XIO(Local_Control.6)EQU(K50ProTouch.Command,2)BTD(Port_Data.Data_Transfer[1],0,K50ProTouch.Read_Data.Master_Cycle_Time,0,8)BTD(Port_Data.Data_Transfer[2],0,K50ProTouch.Read_Data.Min_Cycle_Time,0,8)BTD(Port_Data.Data_Transfer[3],0,K50ProTouch.Read_Data.M_Sequence_Capability,0,8)BTD(Port_Data.Data_Transfer[4],0,K50ProTouch.Read_Data.IO_Link_Version_ID,0,8)BTD(Port_Data.Data_Transfer[5],0,K50ProTouch.Read_Data.Process_Data_Input_Length,0,8)BTD(Port_Data.Data_Transfer[6],0,K50ProTouch.Read_Data.Process_Data_Output_Length,0,8)BTD(Port_Data.Data_Transfer[7],0,K50ProTouch.Read_Data.Combined_Vendor_ID,8,8)BTD(Port_Data.Data_Transfer[8],0,K50ProTouch.Read_Data.Combined_Vendor_ID,0,8)MOV(Port_Data.Data_Transfer[7],K50ProTouch.Read_Data.Vendor_ID1)MOV(Port_Data.Data_Transfer[8],K50ProTouch.Read_Data.Vendor_ID2)BTD(Port_Data.Data_Transfer[9],0,K50ProTouch.Read_Data.Combined_Device_ID,16,8)BTD(Port_Data.Data_Transfer[10],0,K50ProTouch.Read_Data.Combined_Device_ID,8,8)BTD(Port_Data.Data_Transfer[11],0,K50ProTouch.Read_Data.Combined_Device_ID,0,8)MOV(Port_Data.Data_Transfer[9],K50ProTouch.Read_Data.Device_ID1)MOV(Port_Data.Data_Transfer[10],K50ProTouch.Read_Data.Device_ID2)MOV(Port_Data.Data_Transfer[11],K50ProTouch.Read_Data.Device_ID3)OTU(Port_Data.Port_Read.[Port])OTL(Local_Control.6);
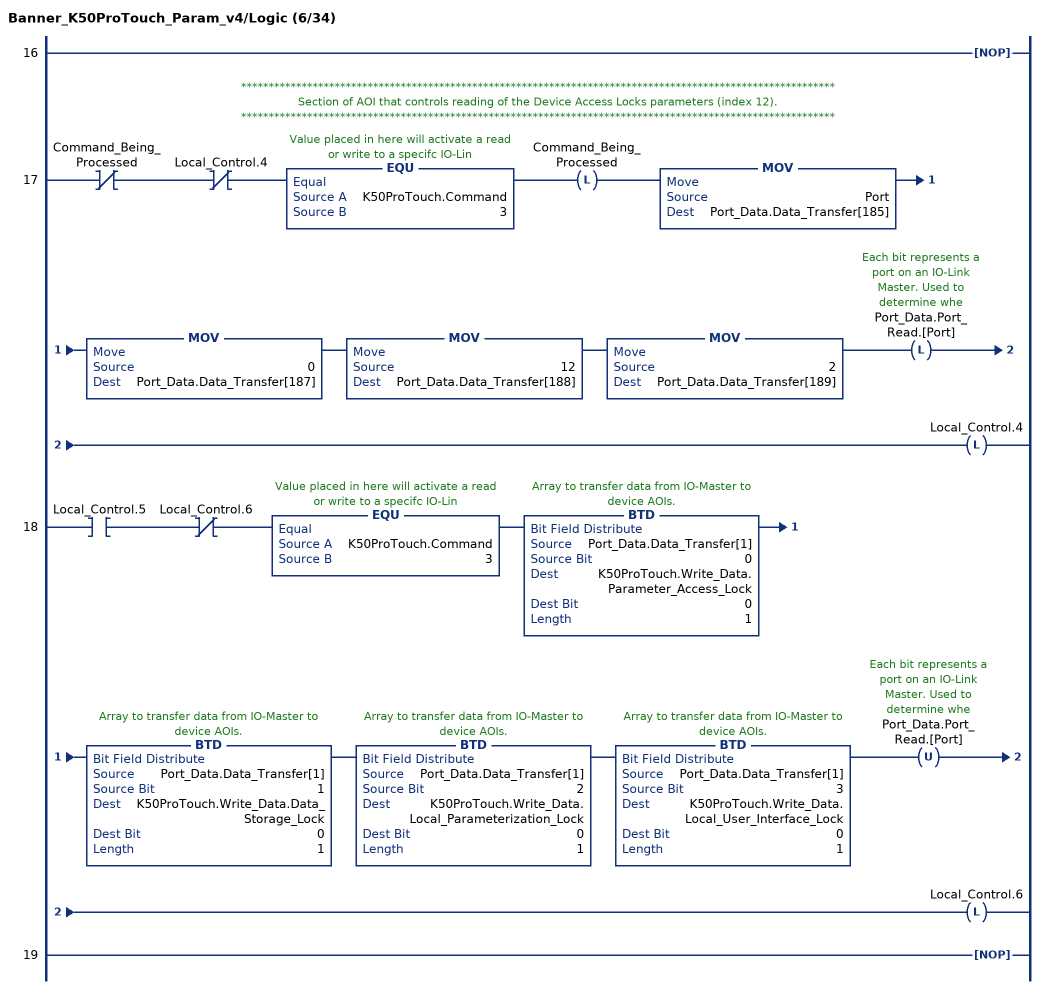
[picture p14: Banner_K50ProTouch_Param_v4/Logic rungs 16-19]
   16: NOP();
   // ************************************************************************************************************
   // Section of AOI that controls reading of the Device Access Locks parameters (index 12).
   // ************************************************************************************************************
   17: XIO(Command_Being_Processed)XIO(Local_Control.4)EQU(K50ProTouch.Command,3)OTL(Command_Being_Processed)MOV(Port,Port_Data.Data_Transfer[185])MOV(0,Port_Data.Data_Transfer[187])MOV(12,Port_Data.Data_Transfer[188])MOV(2,Port_Data.Data_Transfer[189])OTL(Port_Data.Port_Read.[Port])OTL(Local_Control.4);
   18: XIC(Local_Control.5)XIO(Local_Control.6)EQU(K50ProTouch.Command,3)BTD(Port_Data.Data_Transfer[1],0,K50ProTouch.Write_Data.Parameter_Access_Lock,0,1)BTD(Port_Data.Data_Transfer[1],1,K50ProTouch.Write_Data.Data_Storage_Lock,0,1)BTD(Port_Data.Data_Transfer[1],2,K50ProTouch.Write_Data.Local_Parameterization_Lock,0,1)BTD(Port_Data.Data_Transfer[1],3,K50ProTouch.Write_Data.Local_User_Interface_Lock,0,1)OTU(Port_Data.Port_Read.[Port])OTL(Local_Control.6);
   19: NOP();
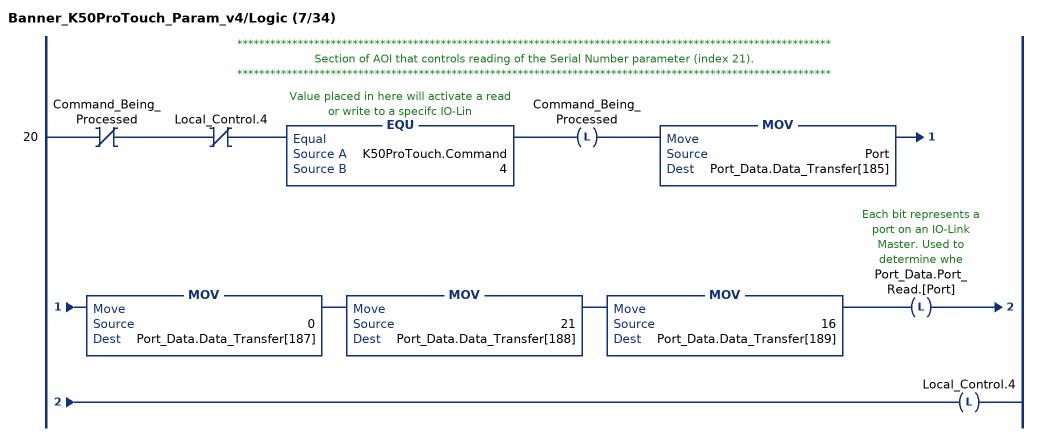
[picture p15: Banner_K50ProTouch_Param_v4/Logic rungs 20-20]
   // ************************************************************************************************************
   // Section of AOI that controls reading of the Serial Number parameter (index 21).
   // ************************************************************************************************************
   20: XIO(Command_Being_Processed)XIO(Local_Control.4)EQU(K50ProTouch.Command,4)OTL(Command_Being_Processed)MOV(Port,Port_Data.Data_Transfer[185])MOV(0,Port_Data.Data_Transfer[187])MOV(21,Port_Data.Data_Transfer[188])MOV(16,Port_Data.Data_Transfer[189])OTL(Port_Data.Port_Read.[Port])OTL(Local_Control.4);
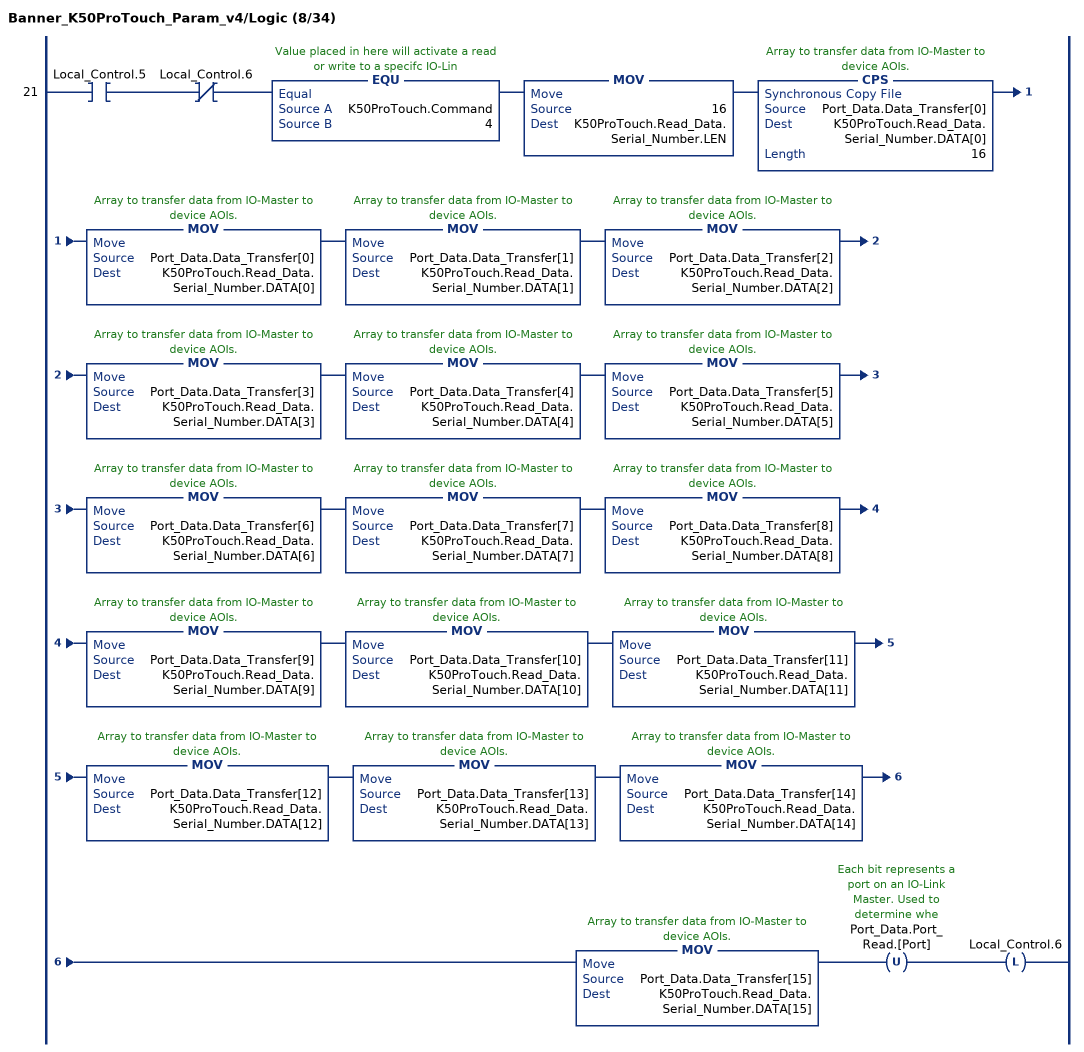
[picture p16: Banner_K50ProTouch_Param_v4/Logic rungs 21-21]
   21: XIC(Local_Control.5)XIO(Local_Control.6)EQU(K50ProTouch.Command,4)MOV(16,K50ProTouch.Read_Data.Serial_Number.LEN)CPS(Port_Data.Data_Transfer[0],K50ProTouch.Read_Data.Serial_Number.DATA[0],16)MOV(Port_Data.Data_Transfer[0],K50ProTouch.Read_Data.Serial_Number.DATA[0])MOV(Port_Data.Data_Transfer[1],K50ProTouch.Read_Data.Serial_Number.DATA[1])MOV(Port_Data.Data_Transfer[2],K50ProTouch.Read_Data.Serial_Number.DATA[2])MOV(Port_Data.Data_Transfer[3],K50ProTouch.Read_Data.Serial_Number.DATA[3])MOV(Port_Data.Data_Transfer[4],K50ProTouch.Read_Data.Serial_Number.DATA[4])MOV(Port_Data.Data_Transfer[5],K50ProTouch.Read_Data.Serial_Number.DATA[5])MOV(Port_Data.Data_Transfer[6],K50ProTouch.Read_Data.Serial_Number.DATA[6])MOV(Port_Data.Data_Transfer[7],K50ProTouch.Read_Data.Serial_Number.DATA[7])MOV(Port_Data.Data_Transfer[8],K50ProTouch.Read_Data.Serial_Number.DATA[8])MOV(Port_Data.Data_Transfer[9],K50ProTouch.Read_Data.Serial_Number.DATA[9])MOV(Port_Data.Data_Transfer[10],K50ProTouch.Read_Data.Serial_Number.DATA[10])MOV(Port_Data.Data_Transfer[11],K50ProTouch.Read_Data.Serial_Number.DATA[11])MOV(Port_Data.Data_Transfer[12],K50ProTouch.Read_Data.Serial_Number.DATA[12])MOV(Port_Data.Data_Transfer[13],K50ProTouch.Read_Data.Serial_Number.DATA[13])MOV(Port_Data.Data_Transfer[14],K50ProTouch.Read_Data.Serial_Number.DATA[14])MOV(Port_Data.Data_Transfer[15],K50ProTouch.Read_Data.Serial_Number.DATA[15])OTU(Port_Data.Port_Read.[Port])OTL(Local_Control.6);
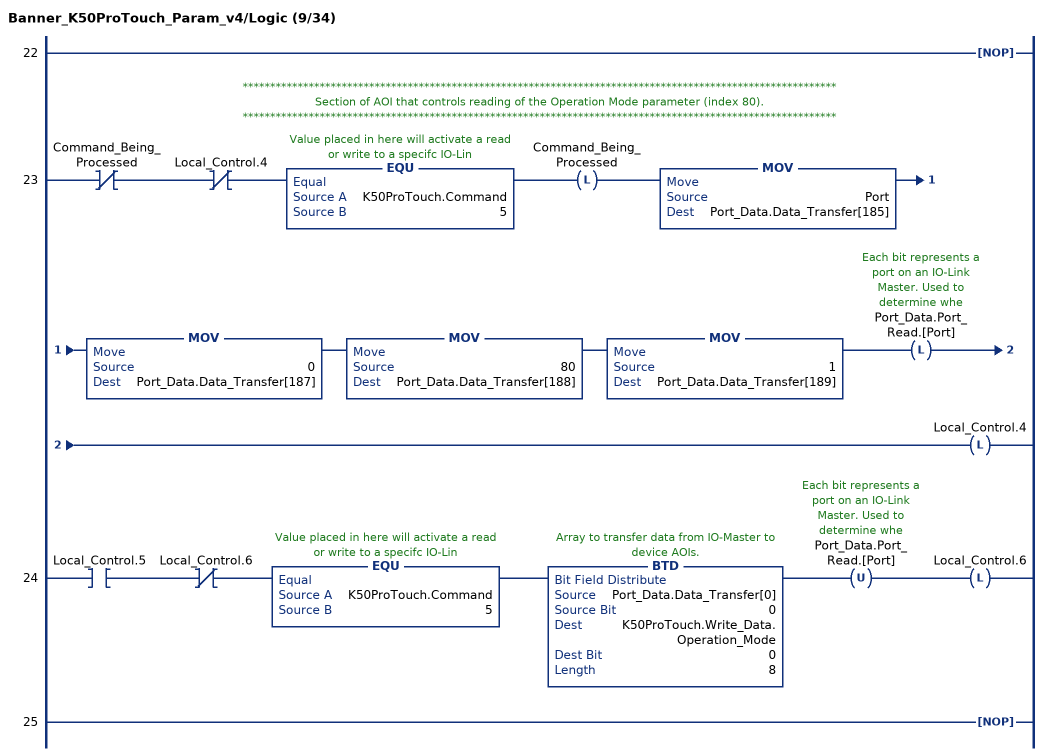
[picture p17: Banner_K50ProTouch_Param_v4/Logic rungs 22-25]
   22: NOP();
   // ************************************************************************************************************
   // Section of AOI that controls reading of the Operation Mode parameter (index 80).
   // ************************************************************************************************************
   23: XIO(Command_Being_Processed)XIO(Local_Control.4)EQU(K50ProTouch.Command,5)OTL(Command_Being_Processed)MOV(Port,Port_Data.Data_Transfer[185])MOV(0,Port_Data.Data_Transfer[187])MOV(80,Port_Data.Data_Transfer[188])MOV(1,Port_Data.Data_Transfer[189])OTL(Port_Data.Port_Read.[Port])OTL(Local_Control.4);
   24: XIC(Local_Control.5)XIO(Local_Control.6)EQU(K50ProTouch.Command,5)BTD(Port_Data.Data_Transfer[0],0,K50ProTouch.Write_Data.Operation_Mode,0,8)OTU(Port_Data.Port_Read.[Port])OTL(Local_Control.6);
   25: NOP();
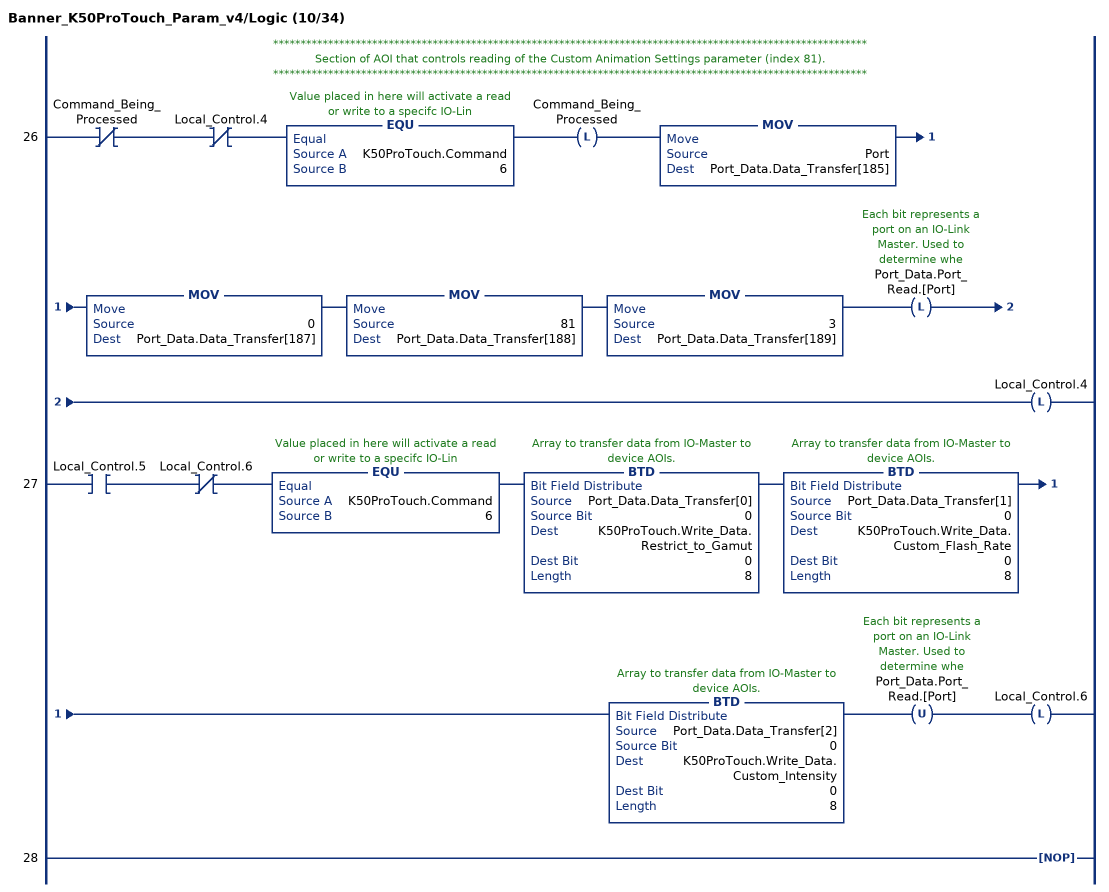
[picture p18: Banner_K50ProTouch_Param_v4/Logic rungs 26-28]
   // ************************************************************************************************************
   // Section of AOI that controls reading of the Custom Animation Settings parameter (index 81).
   // ************************************************************************************************************
   26: XIO(Command_Being_Processed)XIO(Local_Control.4)EQU(K50ProTouch.Command,6)OTL(Command_Being_Processed)MOV(Port,Port_Data.Data_Transfer[185])MOV(0,Port_Data.Data_Transfer[187])MOV(81,Port_Data.Data_Transfer[188])MOV(3,Port_Data.Data_Transfer[189])OTL(Port_Data.Port_Read.[Port])OTL(Local_Control.4);
   27: XIC(Local_Control.5)XIO(Local_Control.6)EQU(K50ProTouch.Command,6)BTD(Port_Data.Data_Transfer[0],0,K50ProTouch.Write_Data.Restrict_to_Gamut,0,8)BTD(Port_Data.Data_Transfer[1],0,K50ProTouch.Write_Data.Custom_Flash_Rate,0,8)BTD(Port_Data.Data_Transfer[2],0,K50ProTouch.Write_Data.Custom_Intensity,0,8)OTU(Port_Data.Port_Read.[Port])OTL(Local_Control.6);
   28: NOP();
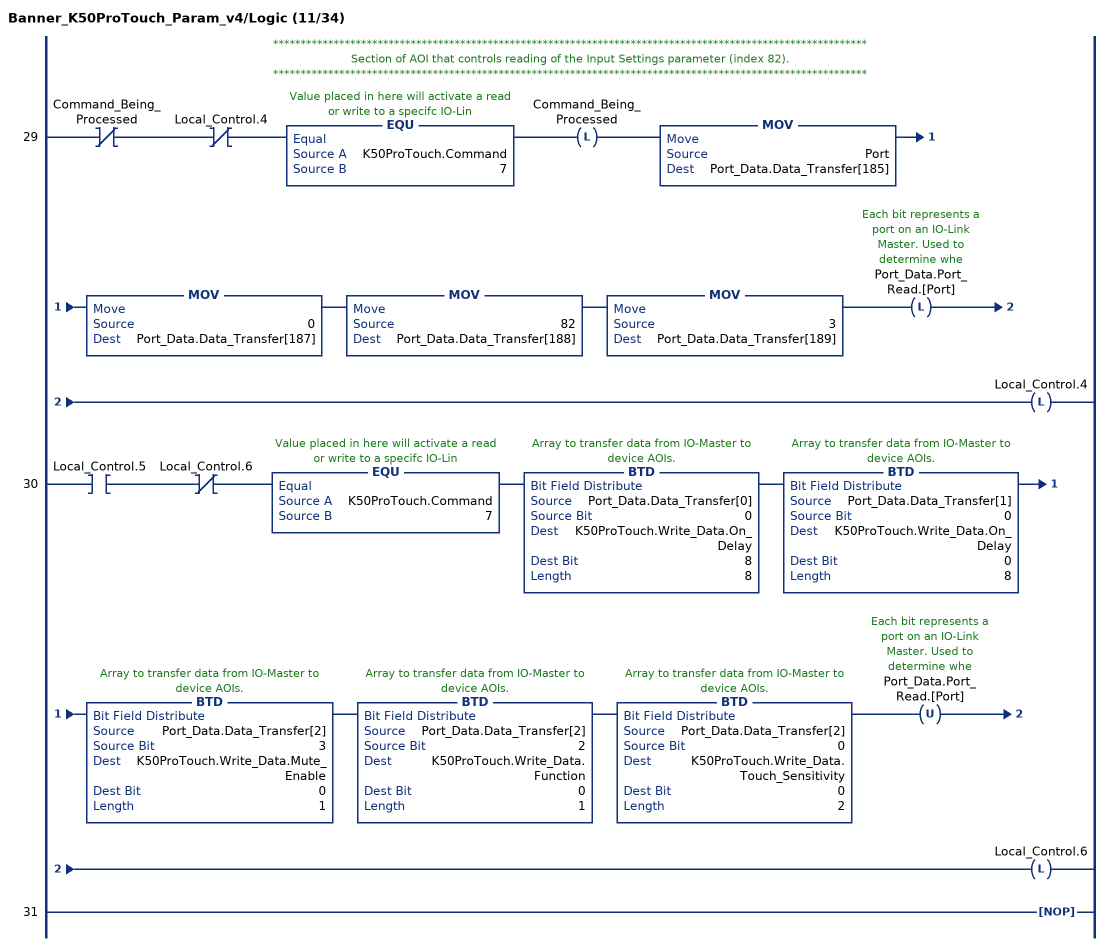
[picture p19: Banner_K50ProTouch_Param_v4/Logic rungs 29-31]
   // ************************************************************************************************************
   // Section of AOI that controls reading of the Input Settings parameter (index 82).
   // ************************************************************************************************************
   29: XIO(Command_Being_Processed)XIO(Local_Control.4)EQU(K50ProTouch.Command,7)OTL(Command_Being_Processed)MOV(Port,Port_Data.Data_Transfer[185])MOV(0,Port_Data.Data_Transfer[187])MOV(82,Port_Data.Data_Transfer[188])MOV(3,Port_Data.Data_Transfer[189])OTL(Port_Data.Port_Read.[Port])OTL(Local_Control.4);
   30: XIC(Local_Control.5)XIO(Local_Control.6)EQU(K50ProTouch.Command,7)BTD(Port_Data.Data_Transfer[0],0,K50ProTouch.Write_Data.On_Delay,8,8)BTD(Port_Data.Data_Transfer[1],0,K50ProTouch.Write_Data.On_Delay,0,8)BTD(Port_Data.Data_Transfer[2],3,K50ProTouch.Write_Data.Mute_Enable,0,1)BTD(Port_Data.Data_Transfer[2],2,K50ProTouch.Write_Data.Function,0,1)BTD(Port_Data.Data_Transfer[2],0,K50ProTouch.Write_Data.Touch_Sensitivity,0,2)OTU(Port_Data.Port_Read.[Port])OTL(Local_Control.6);
   31: NOP();
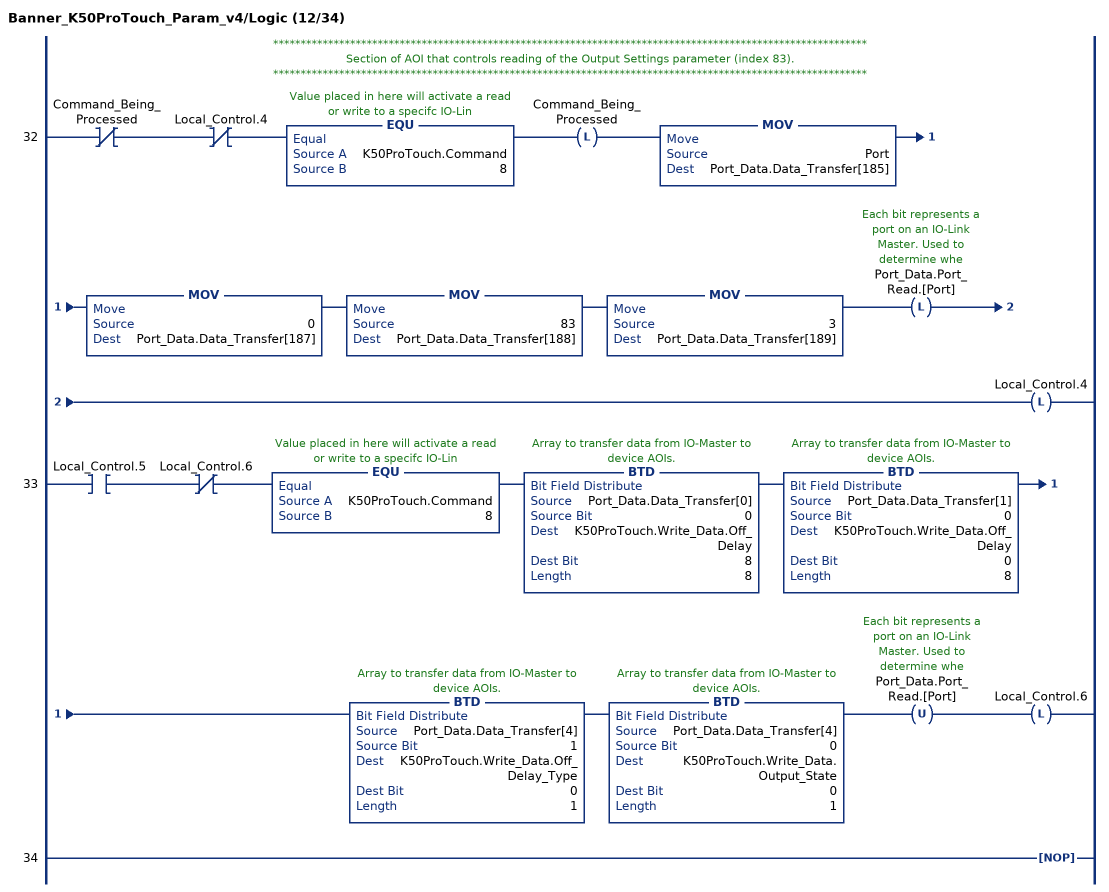
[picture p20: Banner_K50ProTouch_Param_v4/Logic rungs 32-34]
   // ************************************************************************************************************
   // Section of AOI that controls reading of the Output Settings parameter (index 83).
   // ************************************************************************************************************
   32: XIO(Command_Being_Processed)XIO(Local_Control.4)EQU(K50ProTouch.Command,8)OTL(Command_Being_Processed)MOV(Port,Port_Data.Data_Transfer[185])MOV(0,Port_Data.Data_Transfer[187])MOV(83,Port_Data.Data_Transfer[188])MOV(3,Port_Data.Data_Transfer[189])OTL(Port_Data.Port_Read.[Port])OTL(Local_Control.4);
   33: XIC(Local_Control.5)XIO(Local_Control.6)EQU(K50ProTouch.Command,8)BTD(Port_Data.Data_Transfer[0],0,K50ProTouch.Write_Data.Off_Delay,8,8)BTD(Port_Data.Data_Transfer[1],0,K50ProTouch.Write_Data.Off_Delay,0,8)BTD(Port_Data.Data_Transfer[4],1,K50ProTouch.Write_Data.Off_Delay_Type,0,1)BTD(Port_Data.Data_Transfer[4],0,K50ProTouch.Write_Data.Output_State,0,1)OTU(Port_Data.Port_Read.[Port])OTL(Local_Control.6);
   34: NOP();
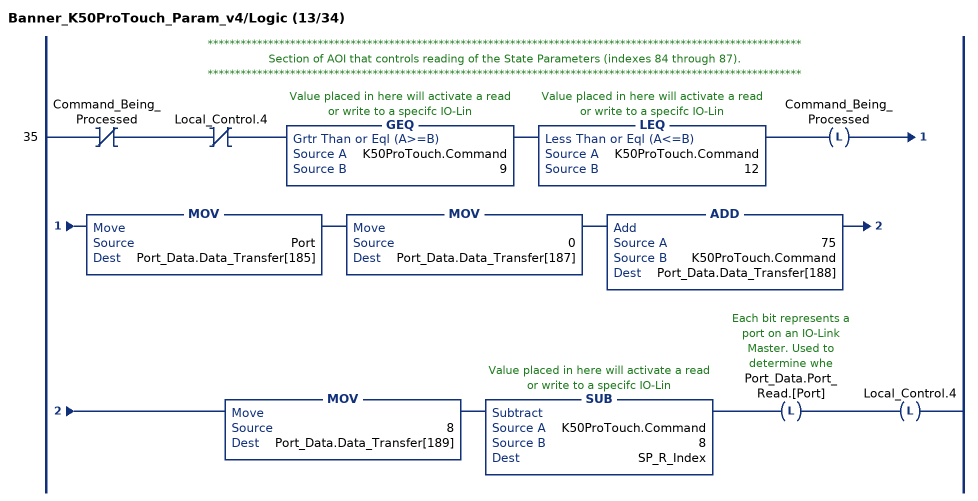
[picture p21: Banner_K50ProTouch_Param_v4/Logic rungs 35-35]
   // ************************************************************************************************************
   // Section of AOI that controls reading of the State Parameters (indexes 84 through 87).
   // ************************************************************************************************************
   35: XIO(Command_Being_Processed)XIO(Local_Control.4)GEQ(K50ProTouch.Command,9)LEQ(K50ProTouch.Command,12)OTL(Command_Being_Processed)MOV(Port,Port_Data.Data_Transfer[185])MOV(0,Port_Data.Data_Transfer[187])ADD(75,K50ProTouch.Command,Port_Data.Data_Transfer[188])MOV(8,Port_Data.Data_Transfer[189])SUB(K50ProTouch.Command,8,SP_R_Index)OTL(Port_Data.Port_Read.[Port])OTL(Local_Control.4);
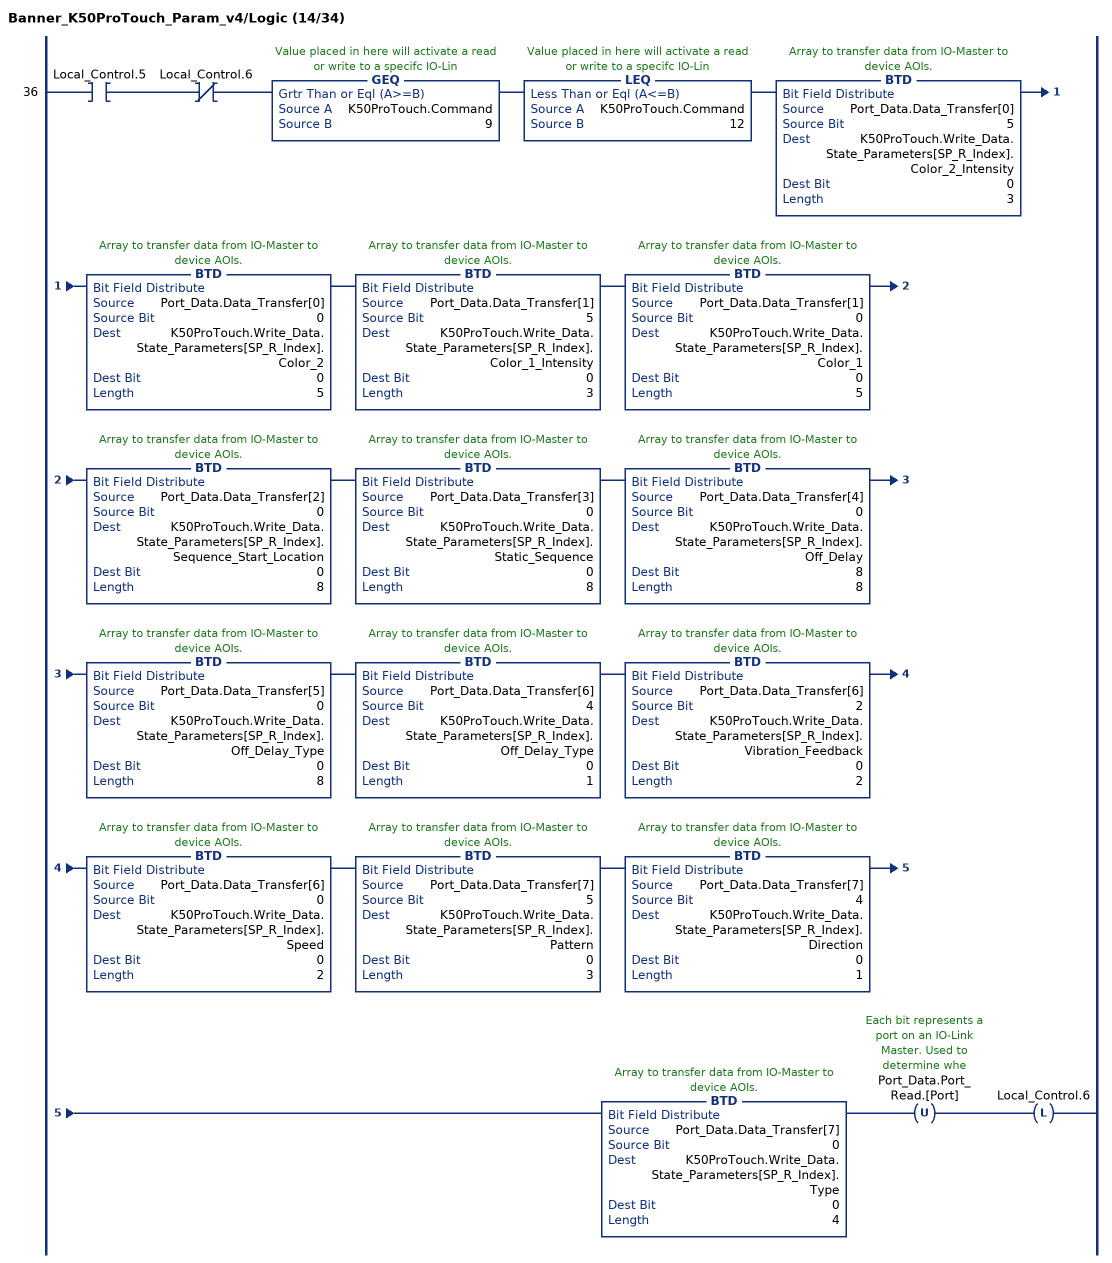
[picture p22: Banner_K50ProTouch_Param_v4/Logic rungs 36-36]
   36: XIC(Local_Control.5)XIO(Local_Control.6)GEQ(K50ProTouch.Command,9)LEQ(K50ProTouch.Command,12)BTD(Port_Data.Data_Transfer[0],5,K50ProTouch.Write_Data.State_Parameters[SP_R_Index].Color_2_Intensity,0,3)BTD(Port_Data.Data_Transfer[0],0,K50ProTouch.Write_Data.State_Parameters[SP_R_Index].Color_2,0,5)BTD(Port_Data.Data_Transfer[1],5,K50ProTouch.Write_Data.State_Parameters[SP_R_Index].Color_1_Intensity,0,3)BTD(Port_Data.Data_Transfer[1],0,K50ProTouch.Write_Data.State_Parameters[SP_R_Index].Color_1,0,5)BTD(Port_Data.Data_Transfer[2],0,K50ProTouch.Write_Data.State_Parameters[SP_R_Index].Sequence_Start_Location,0,8)BTD(Port_Data.Data_Transfer[3],0,K50ProTouch.Write_Data.State_Parameters[SP_R_Index].Static_Sequence,0,8)BTD(Port_Data.Data_Transfer[4],0,K50ProTouch.Write_Data.State_Parameters[SP_R_Index].Off_Delay,8,8)BTD(Port_Data.Data_Transfer[5],0,K50ProTouch.Write_Data.State_Parameters[SP_R_Index].Off_Delay_Type,0,8)BTD(Port_Data.Data_Transfer[6],4,K50ProTouch.Write_Data.State_Parameters[SP_R_Index].Off_Delay_Type,0,1)BTD(Port_Data.Data_Transfer[6],2,K50ProTouch.Write_Data.State_Parameters[SP_R_Index].Vibration_Feedback,0,2)BTD(Port_Data.Data_Transfer[6],0,K50ProTouch.Write_Data.State_Parameters[SP_R_Index].Speed,0,2)BTD(Port_Data.Data_Transfer[7],5,K50ProTouch.Write_Data.State_Parameters[SP_R_Index].Pattern,0,3)BTD(Port_Data.Data_Transfer[7],4,K50ProTouch.Write_Data.State_Parameters[SP_R_Index].Direction,0,1)BTD(Port_Data.Data_Transfer[7],0,K50ProTouch.Write_Data.State_Parameters[SP_R_Index].Type,0,4)OTU(Port_Data.Port_Read.[Port])OTL(Local_Control.6);
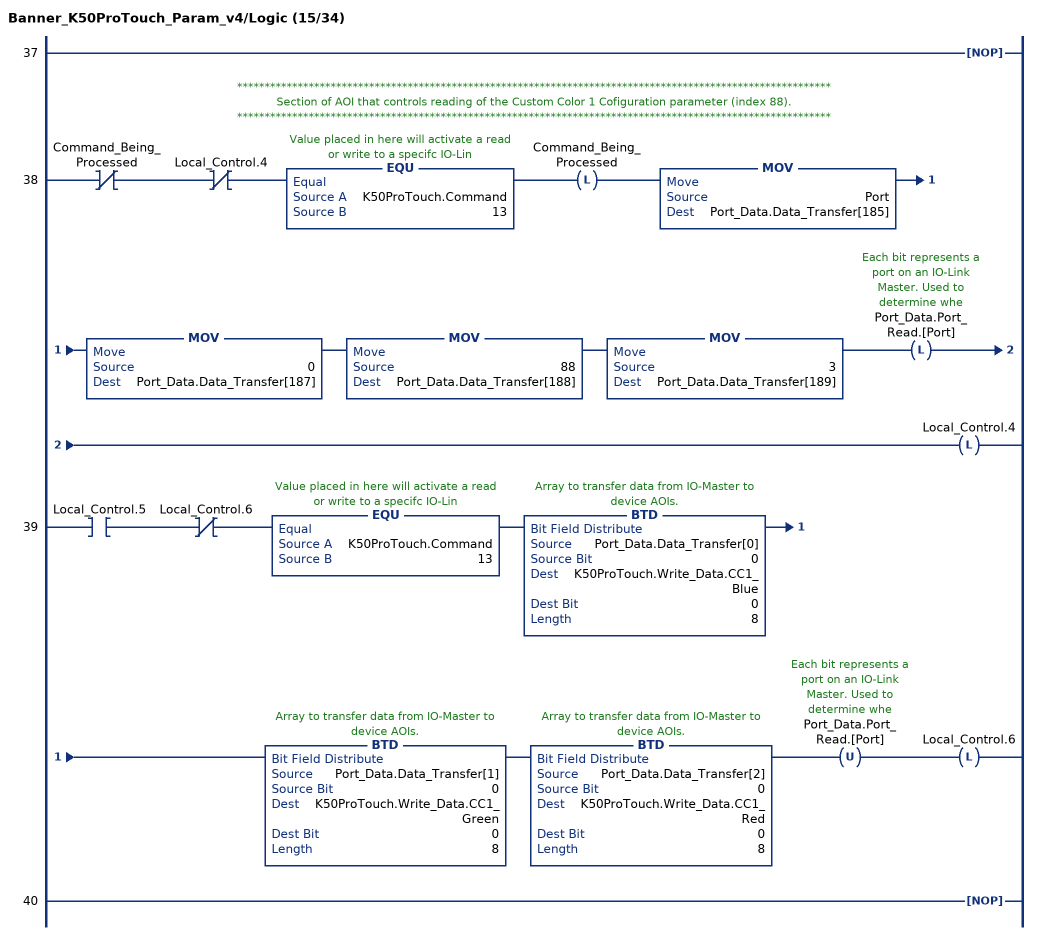
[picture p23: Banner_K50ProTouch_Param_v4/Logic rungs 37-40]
   37: NOP();
   // ************************************************************************************************************
   // Section of AOI that controls reading of the Custom Color 1 Cofiguration parameter (index 88).
   // ************************************************************************************************************
   38: XIO(Command_Being_Processed)XIO(Local_Control.4)EQU(K50ProTouch.Command,13)OTL(Command_Being_Processed)MOV(Port,Port_Data.Data_Transfer[185])MOV(0,Port_Data.Data_Transfer[187])MOV(88,Port_Data.Data_Transfer[188])MOV(3,Port_Data.Data_Transfer[189])OTL(Port_Data.Port_Read.[Port])OTL(Local_Control.4);
   39: XIC(Local_Control.5)XIO(Local_Control.6)EQU(K50ProTouch.Command,13)BTD(Port_Data.Data_Transfer[0],0,K50ProTouch.Write_Data.CC1_Blue,0,8)BTD(Port_Data.Data_Transfer[1],0,K50ProTouch.Write_Data.CC1_Green,0,8)BTD(Port_Data.Data_Transfer[2],0,K50ProTouch.Write_Data.CC1_Red,0,8)OTU(Port_Data.Port_Read.[Port])OTL(Local_Control.6);
   40: NOP();
